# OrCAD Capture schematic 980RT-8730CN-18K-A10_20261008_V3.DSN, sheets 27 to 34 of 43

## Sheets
27 S0097_ATX_POWER: size Custom
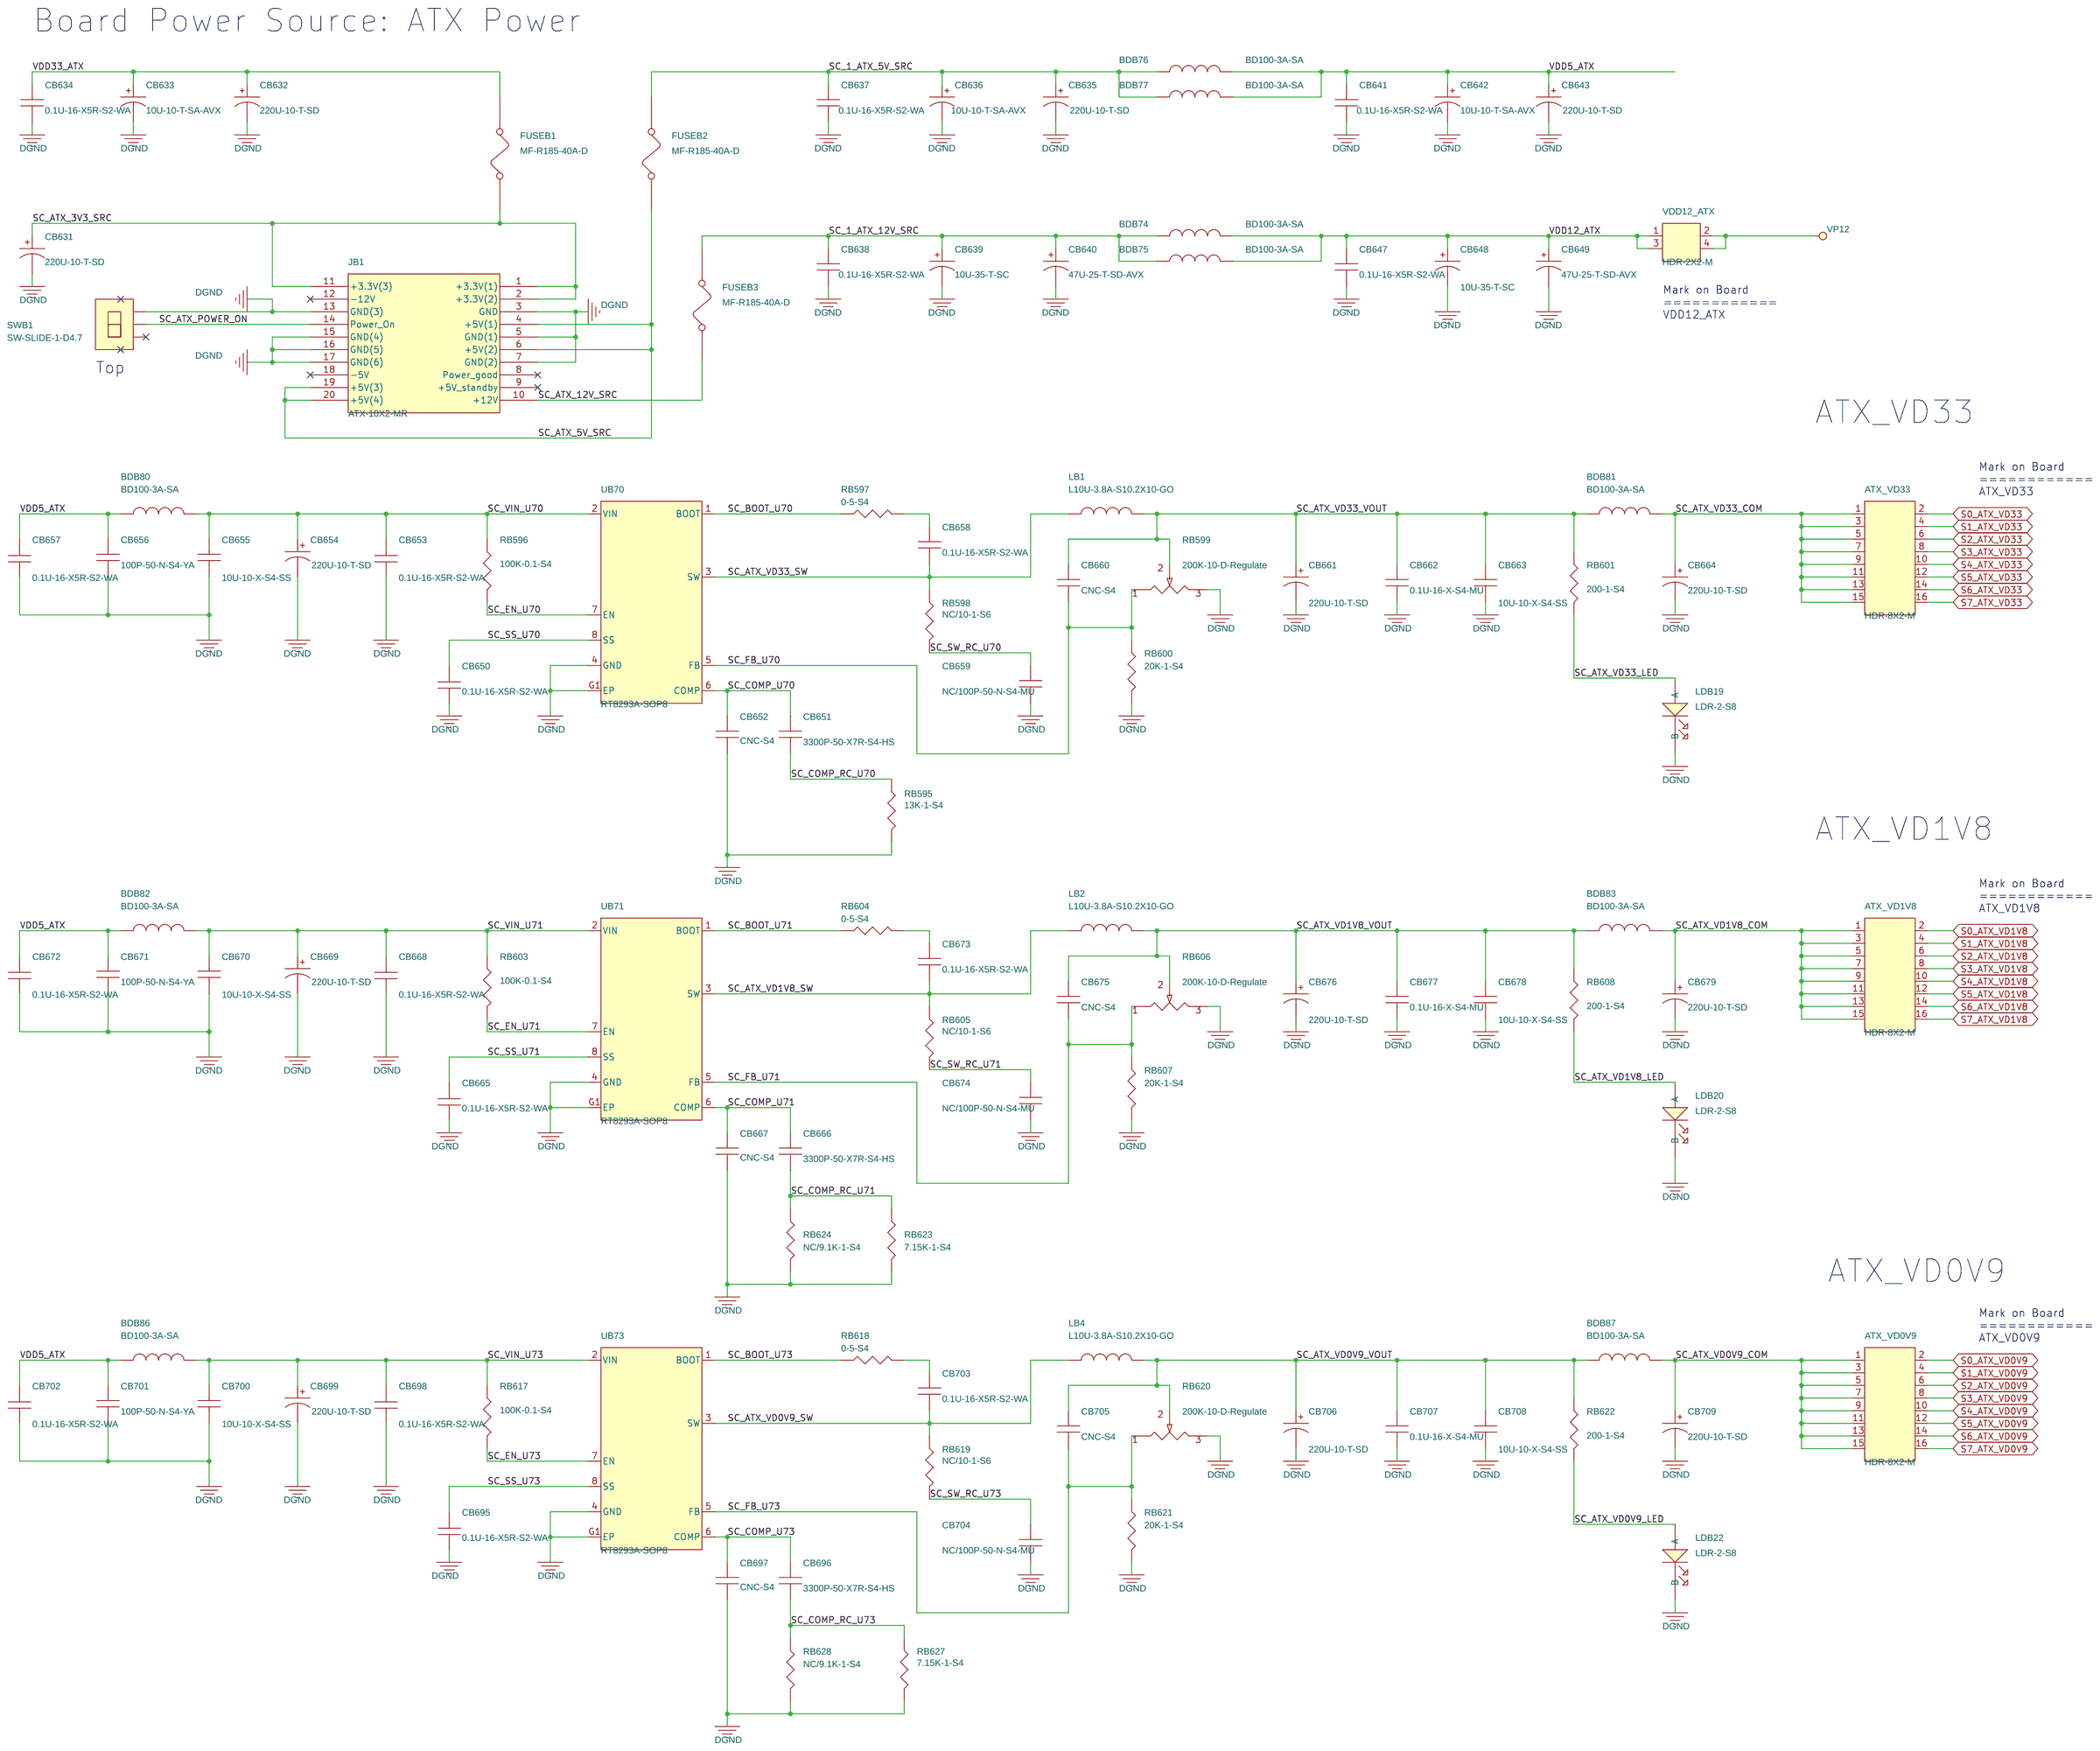
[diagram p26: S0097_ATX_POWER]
28 S0098_128UR: size A2
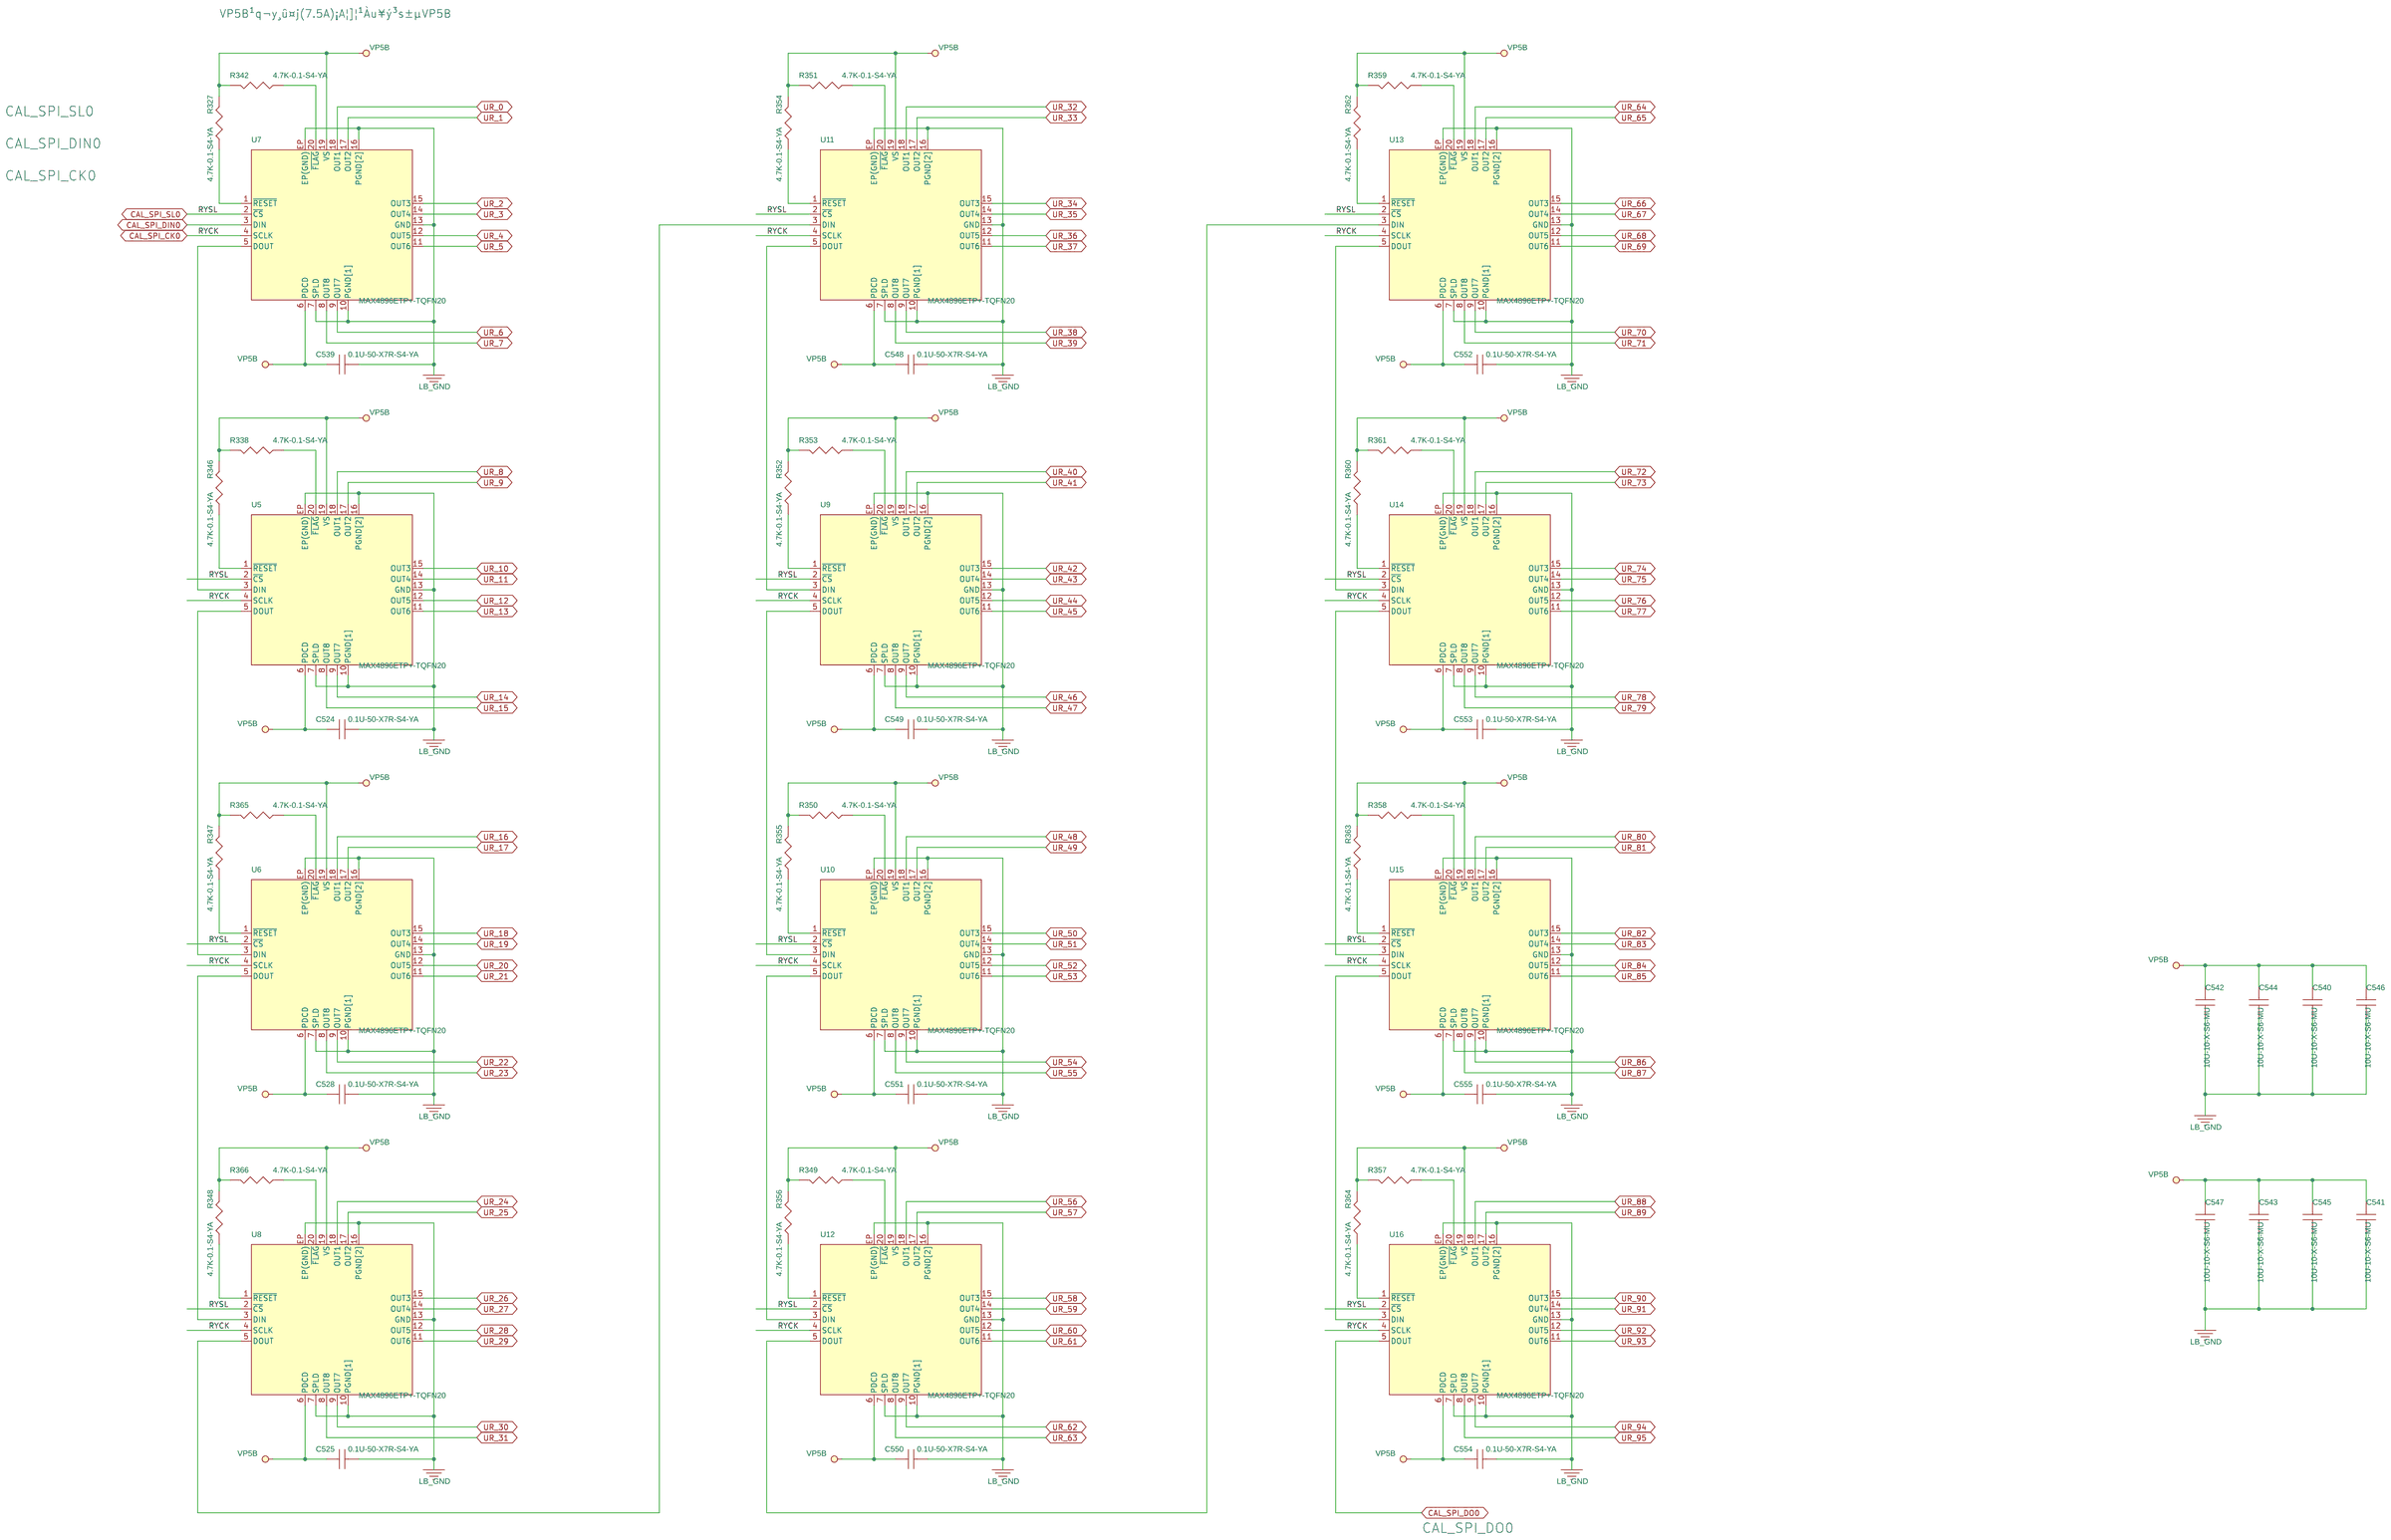
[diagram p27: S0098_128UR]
29 S0099_MISC: size A3
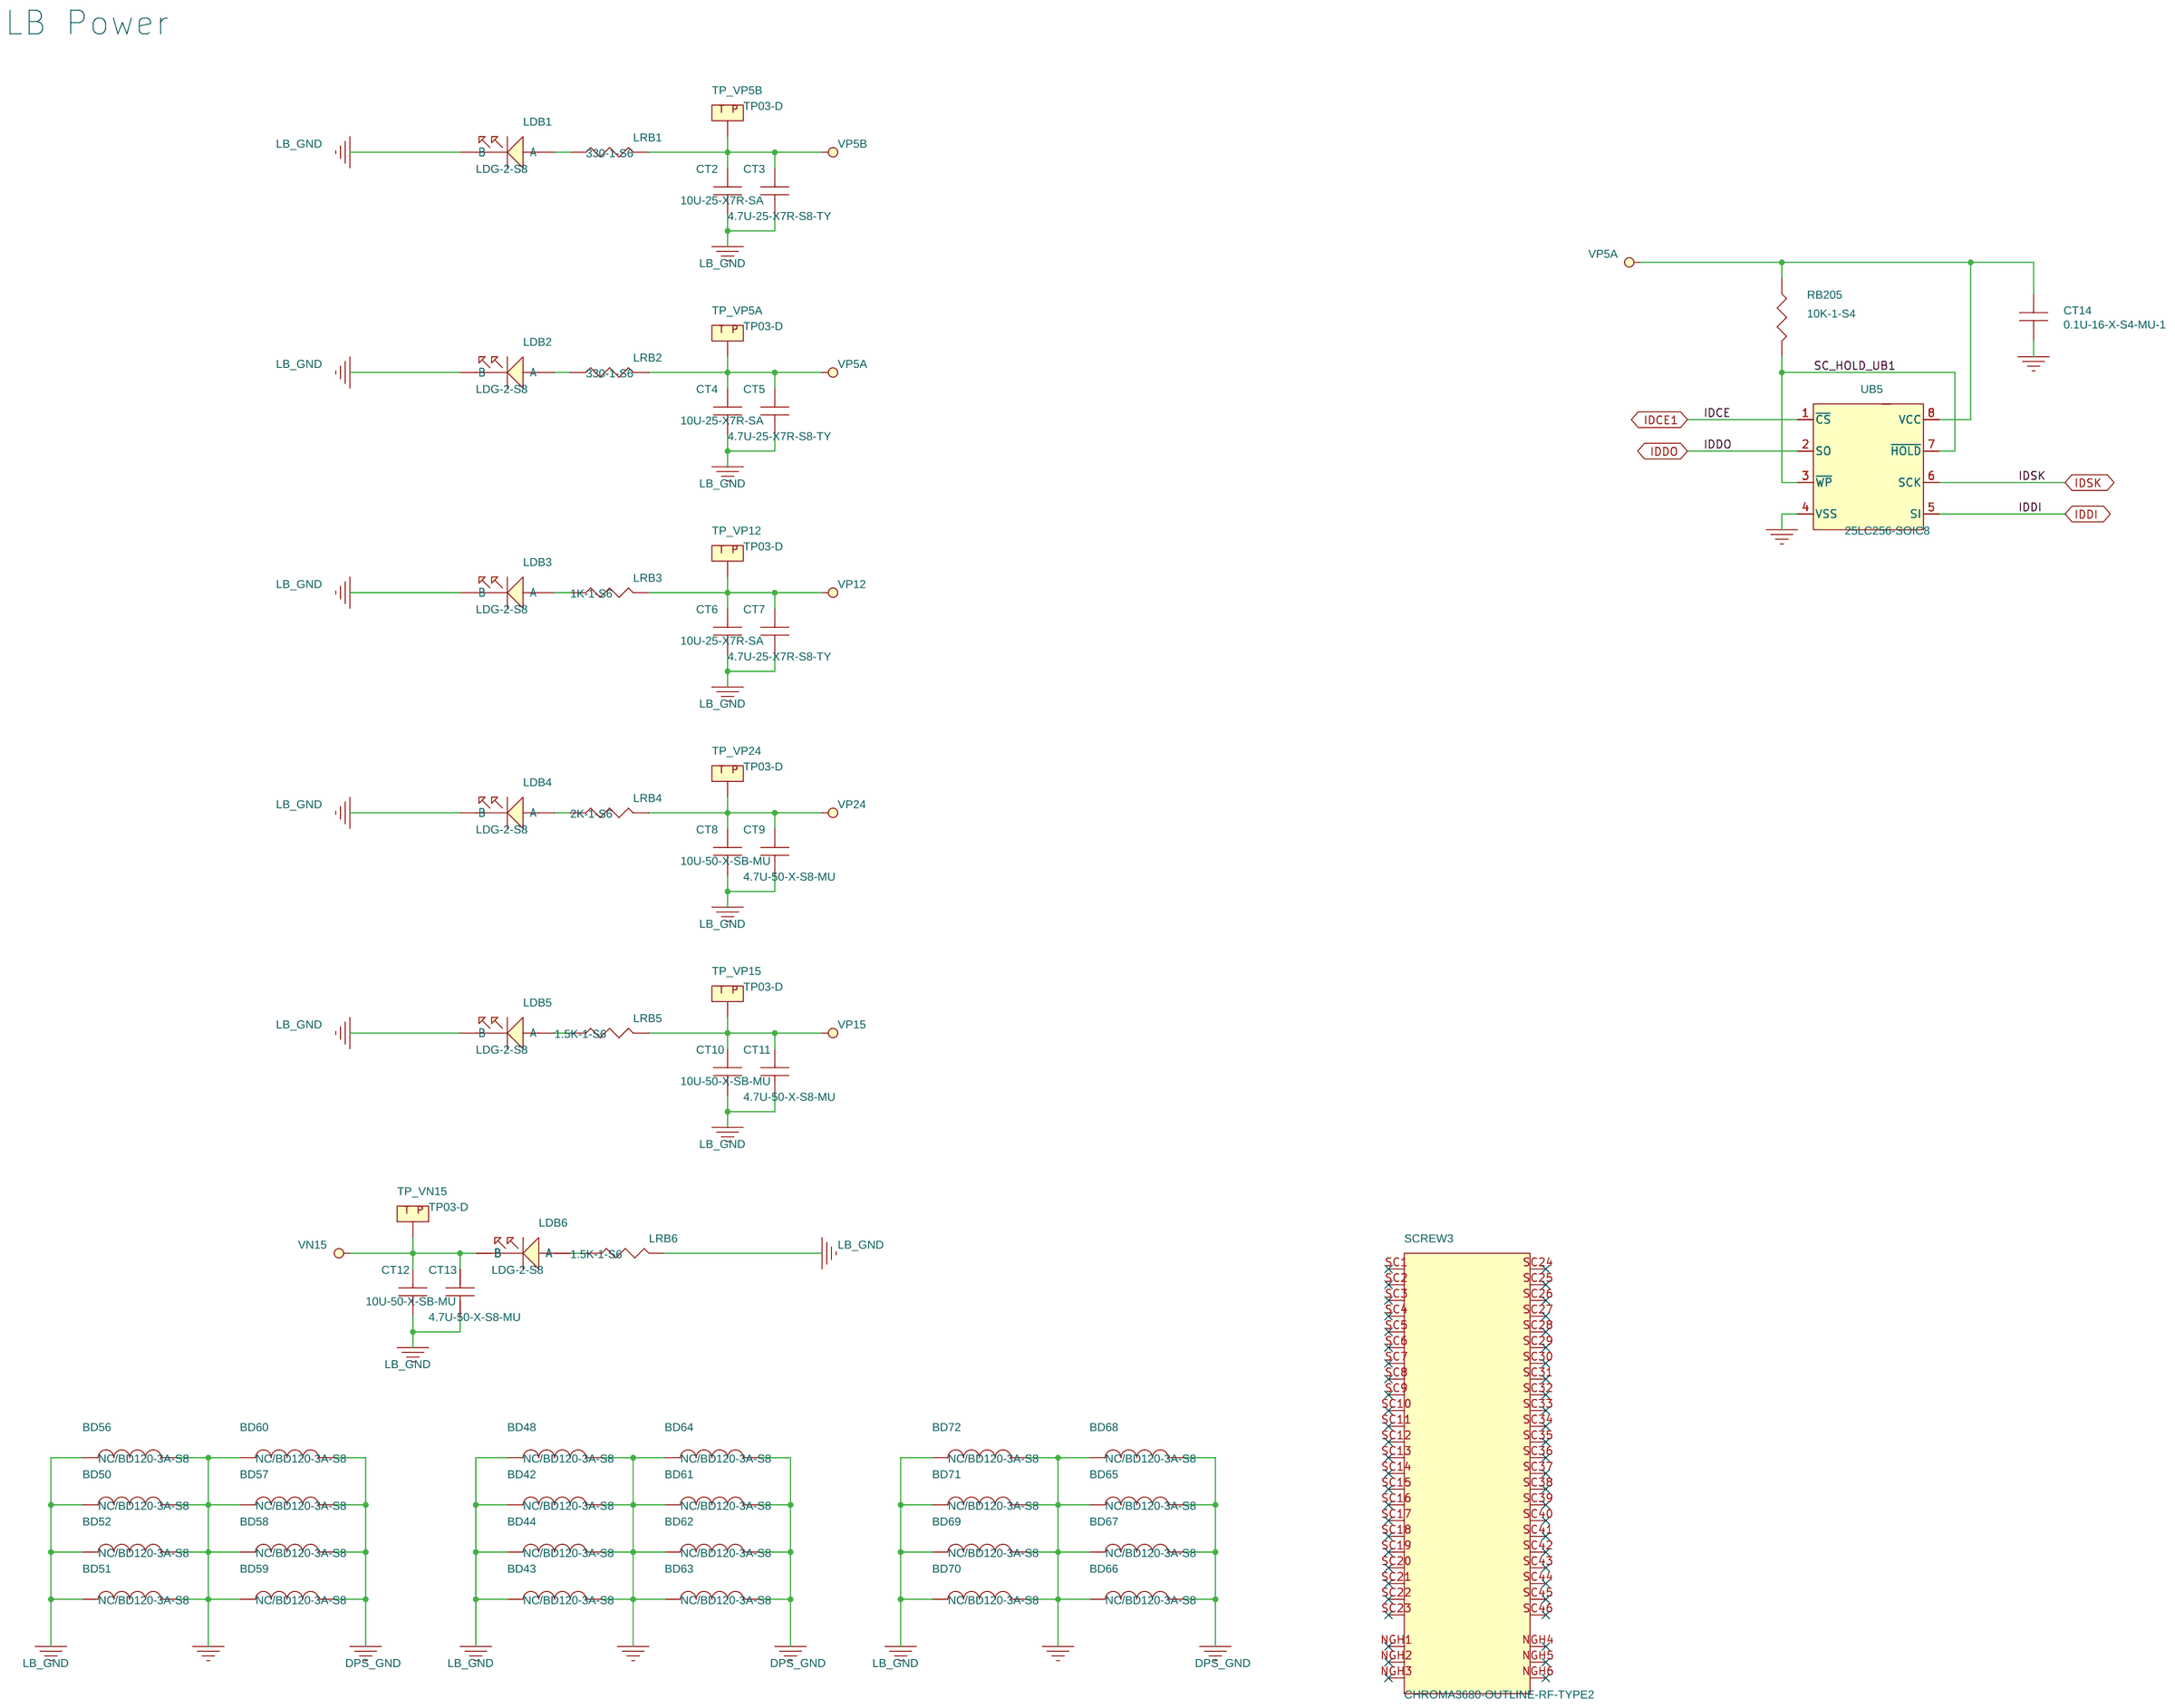
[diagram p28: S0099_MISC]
30 S9999_HOLE: size A
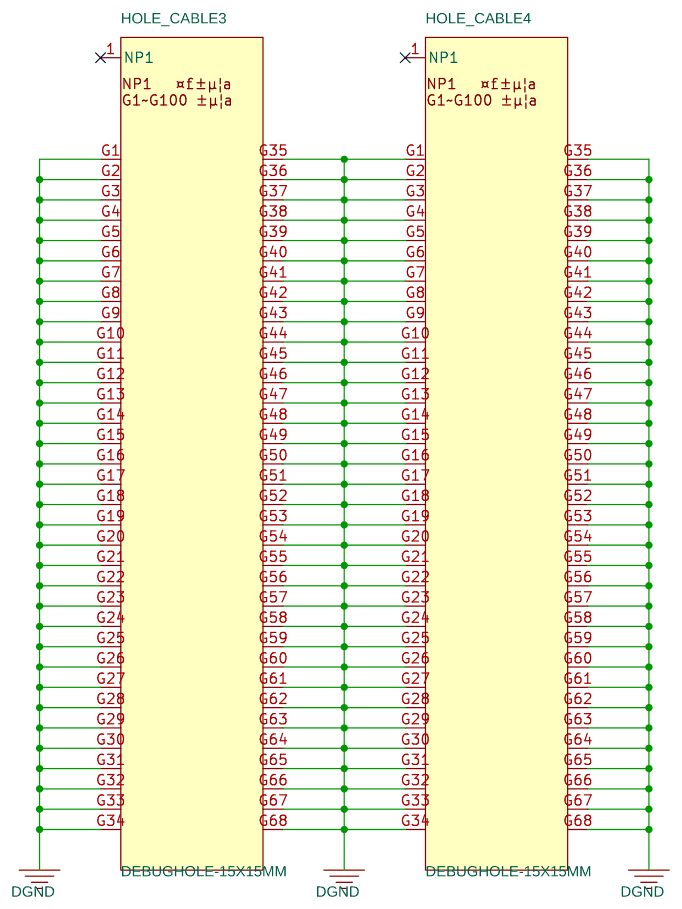
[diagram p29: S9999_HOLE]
31 T01.3680_DPS64_HDAV_H_P1: size Custom
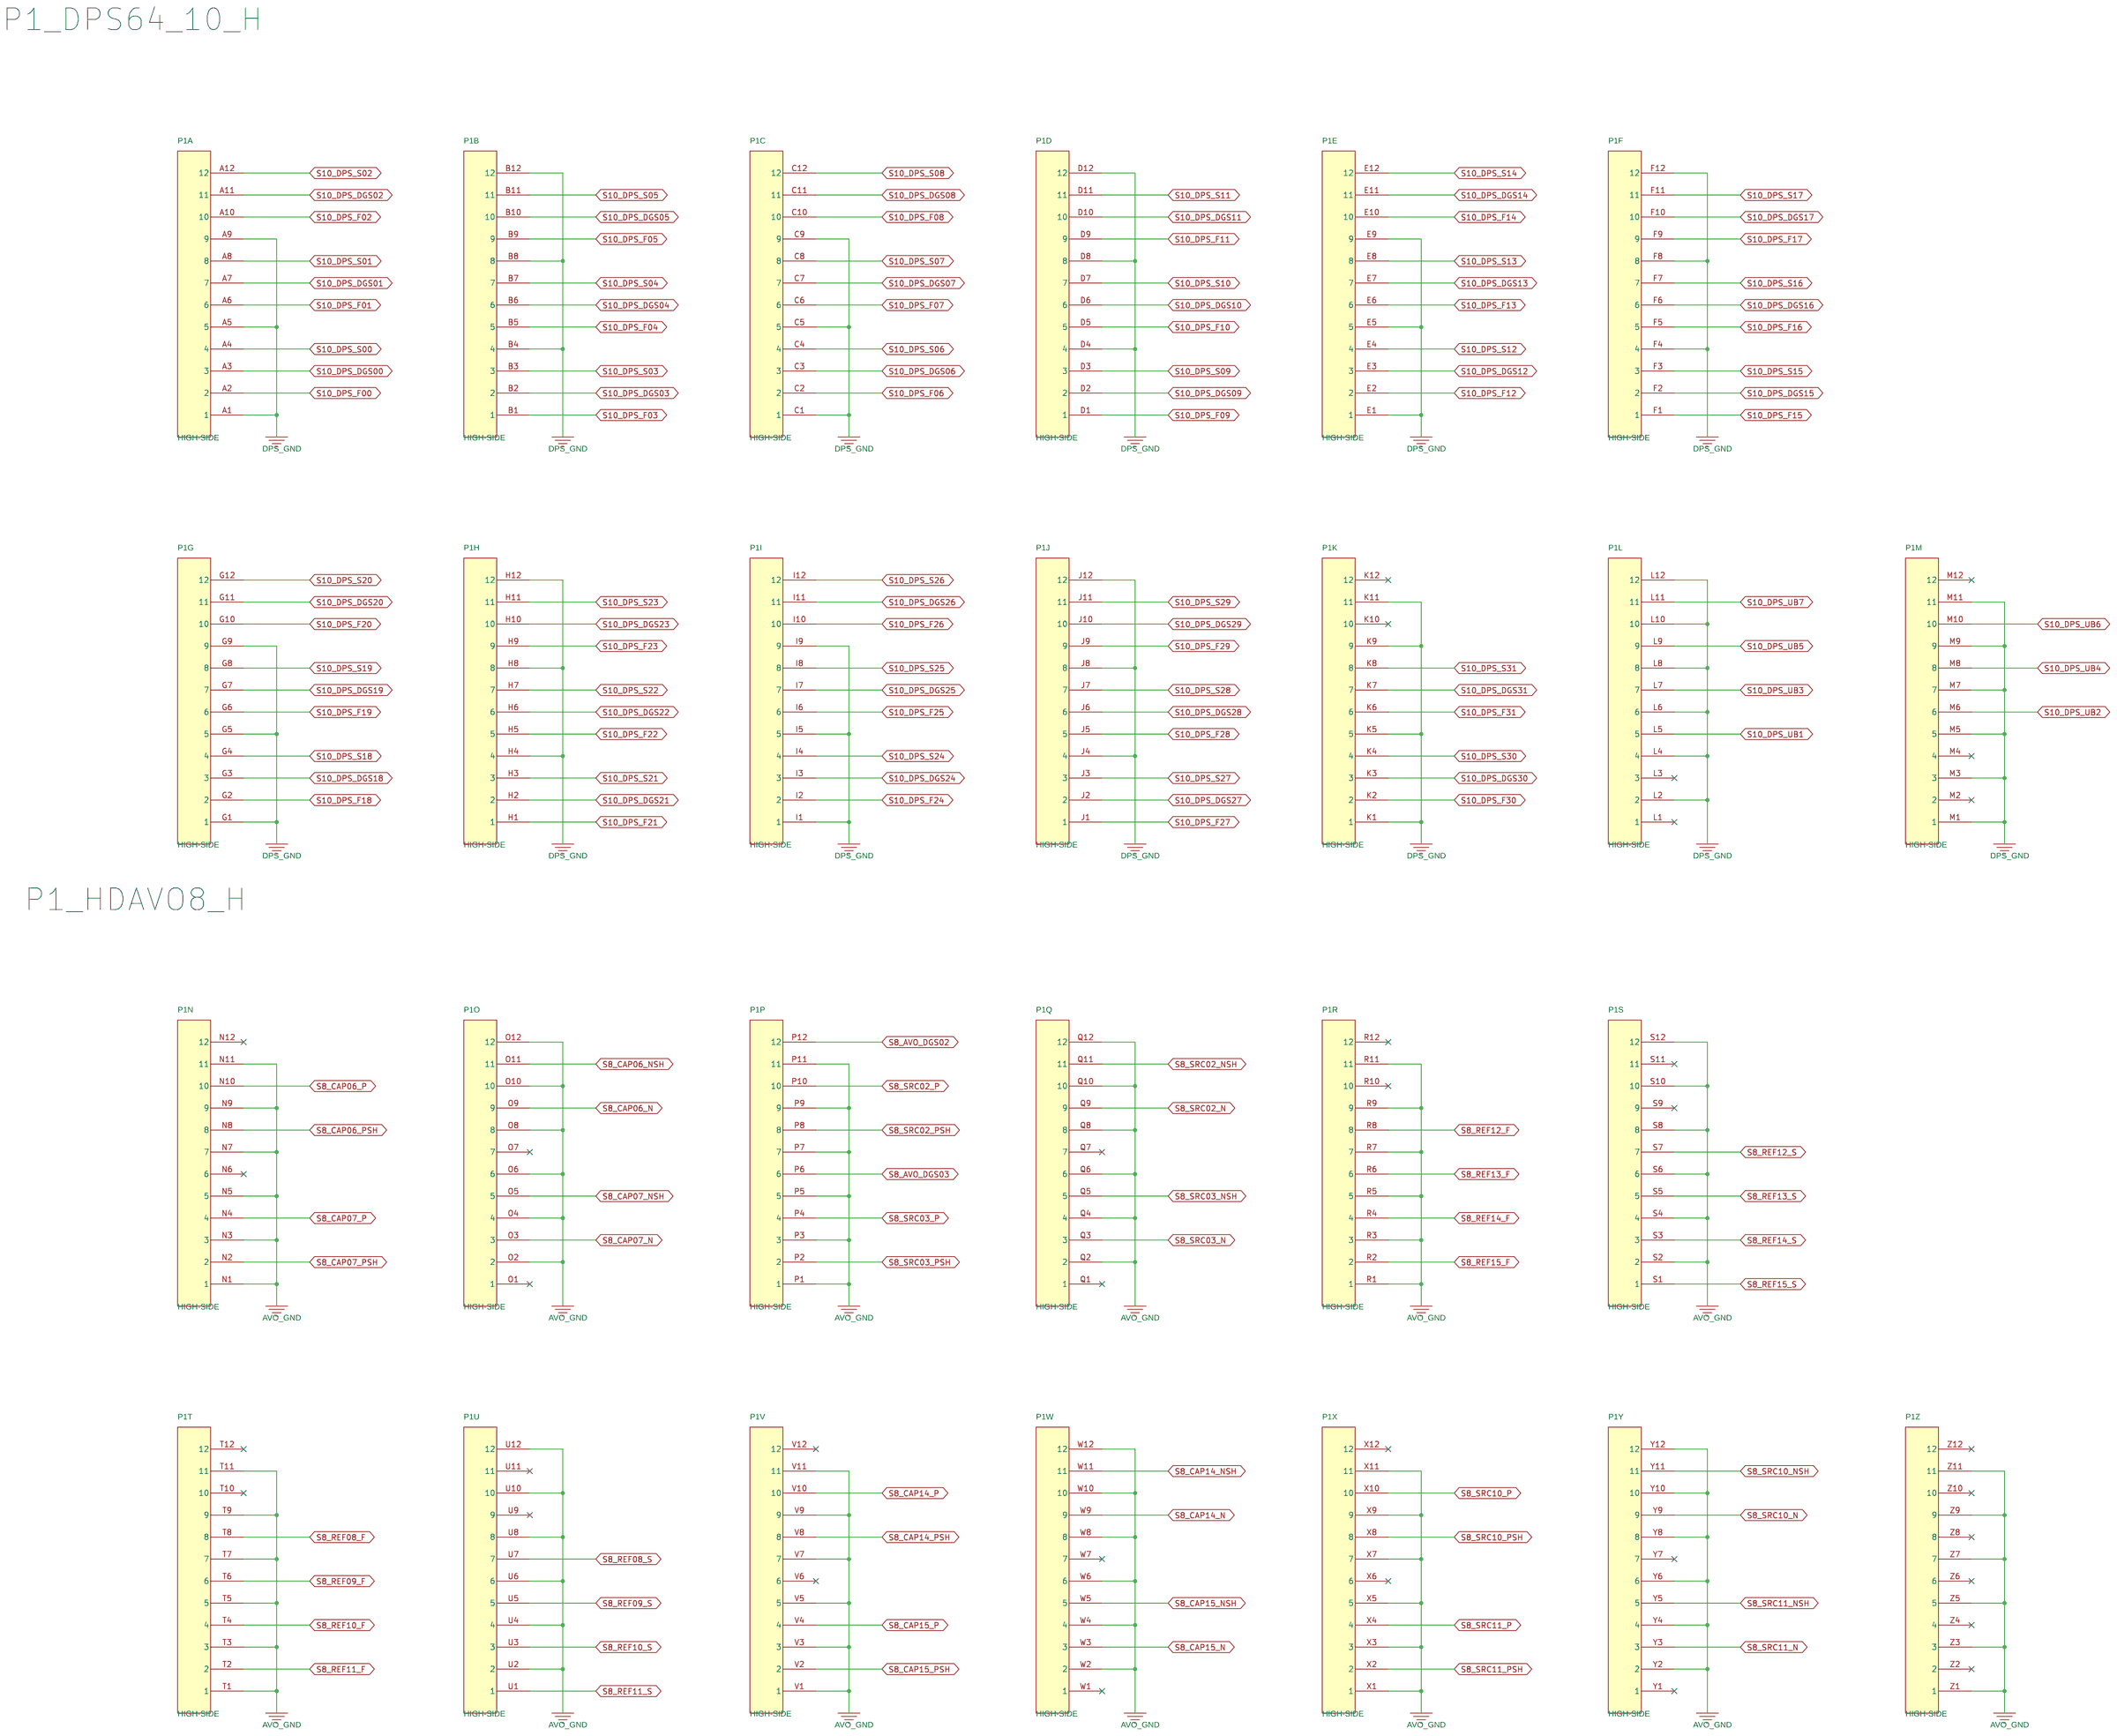
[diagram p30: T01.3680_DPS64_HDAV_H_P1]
32 T02.3680_LPC_P2: size Custom
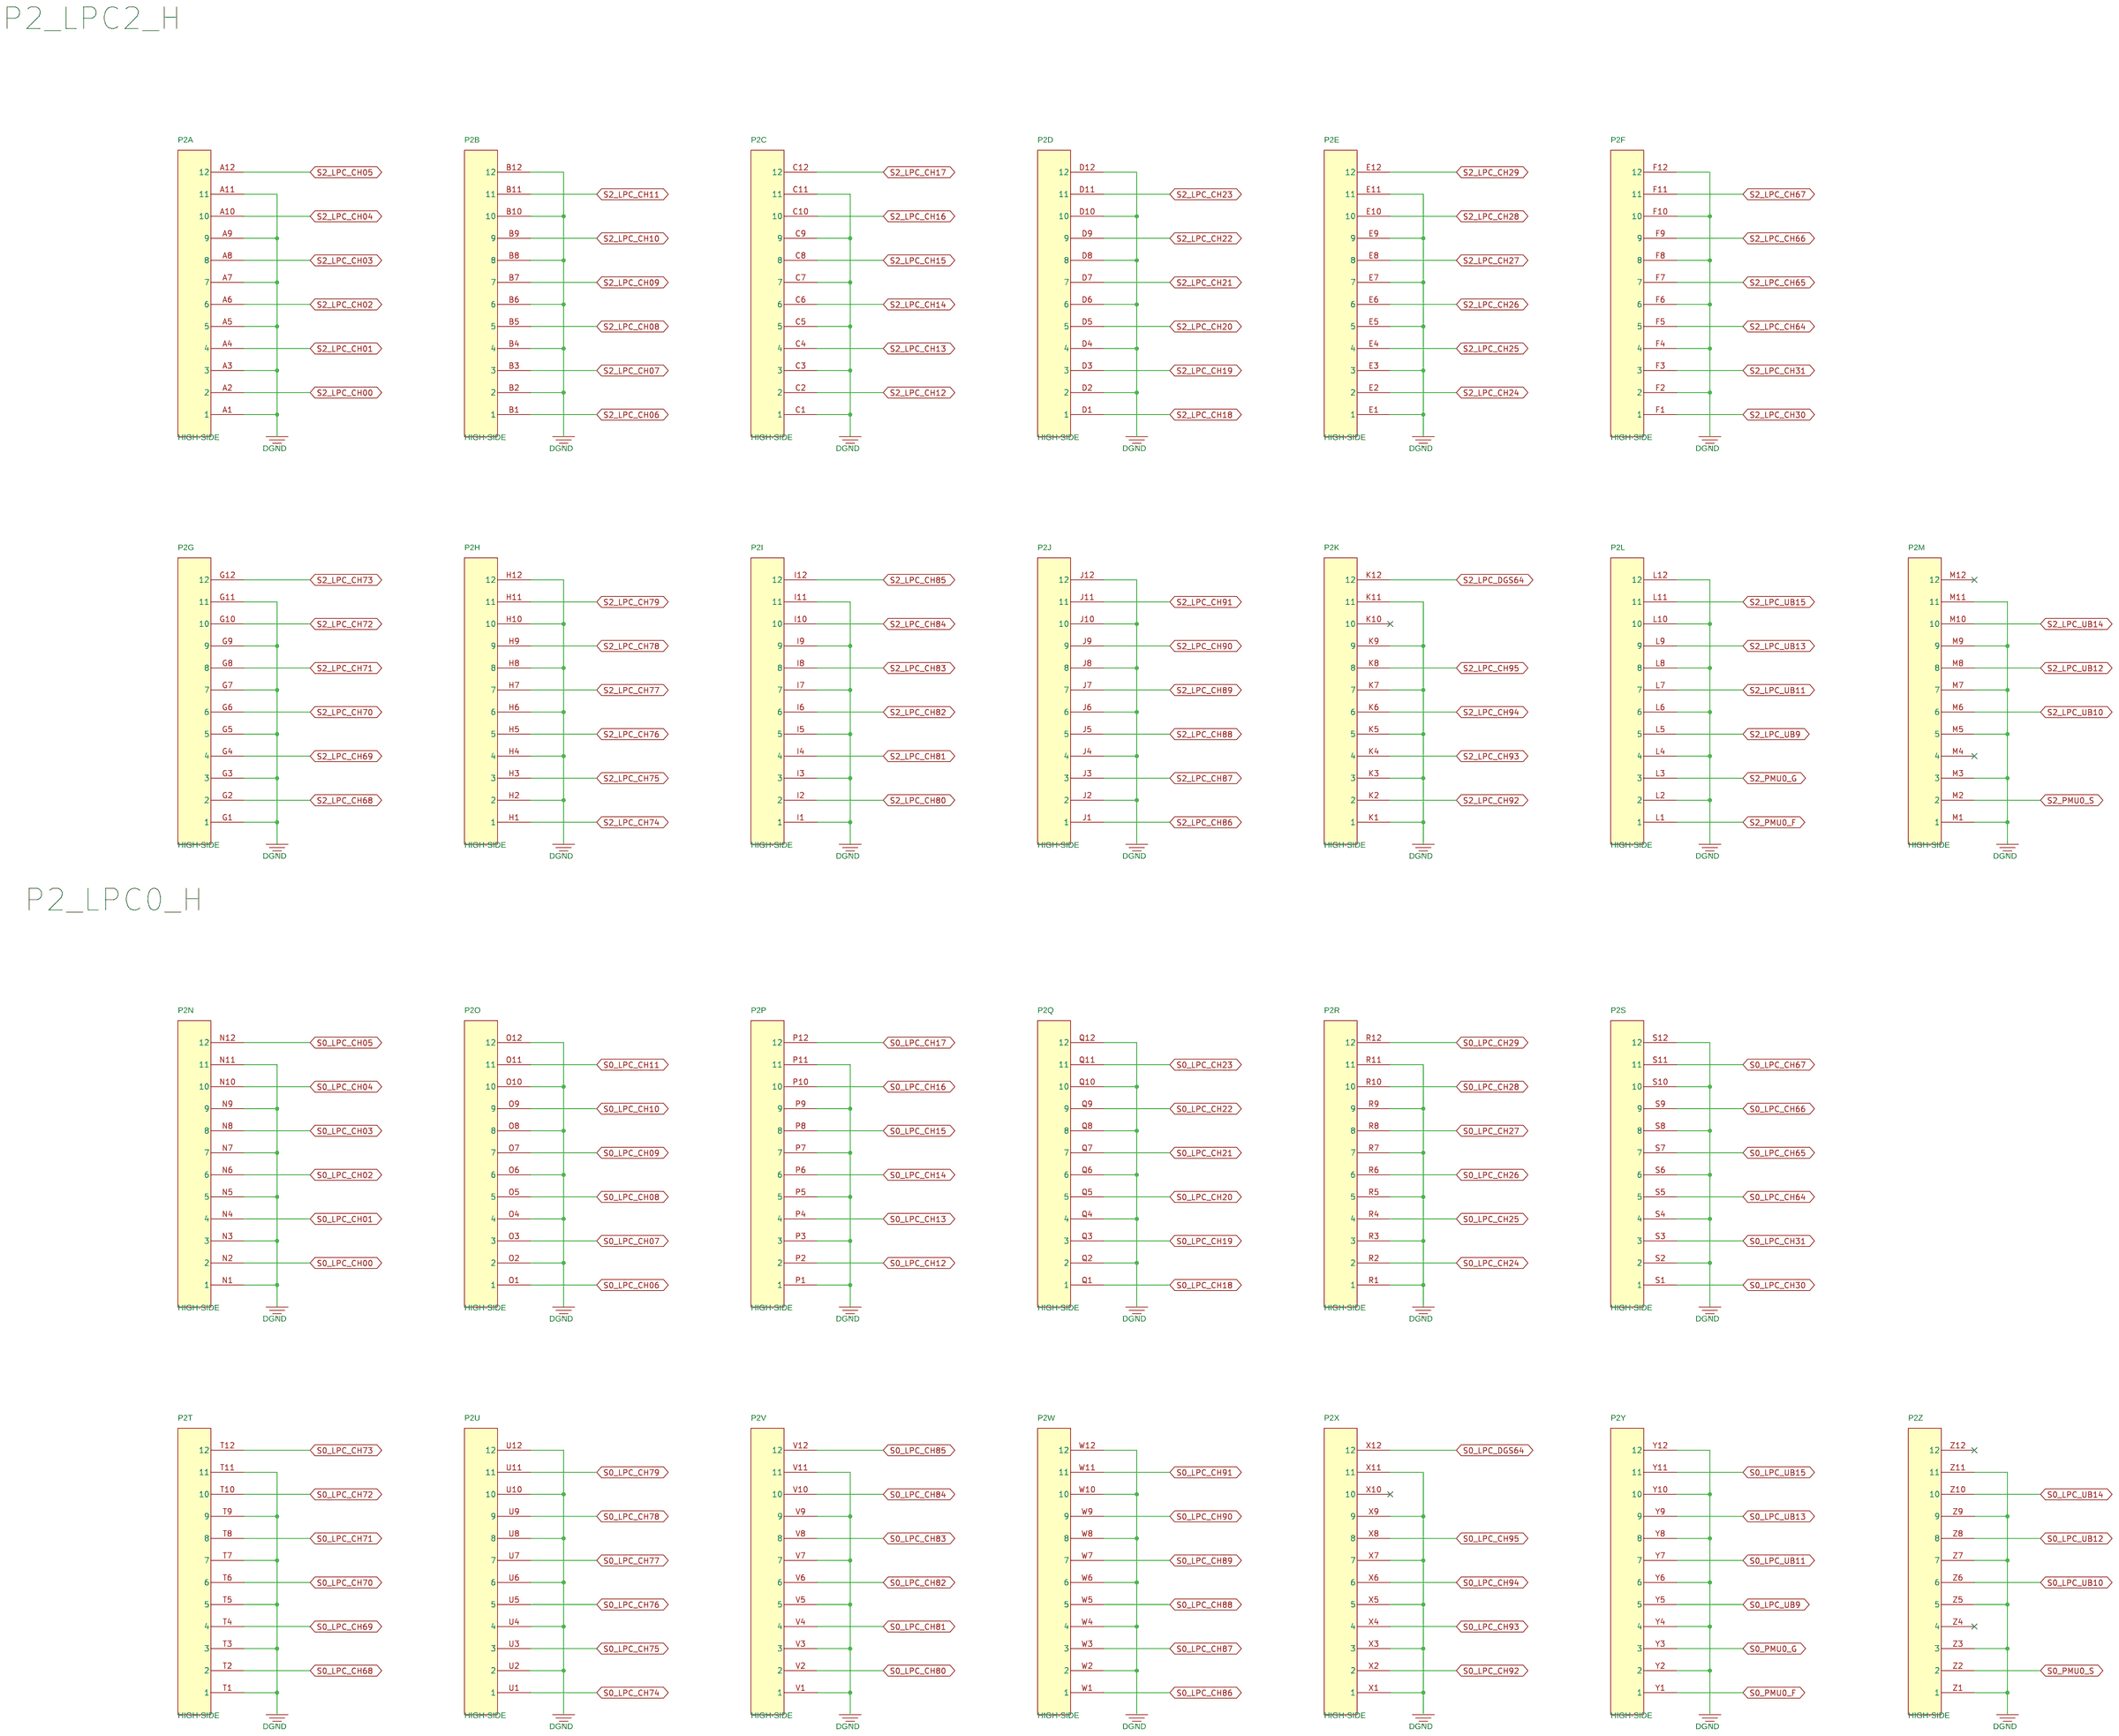
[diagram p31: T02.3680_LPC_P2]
33 T04.3680_DPS64_HDAV_H_P4: size Custom
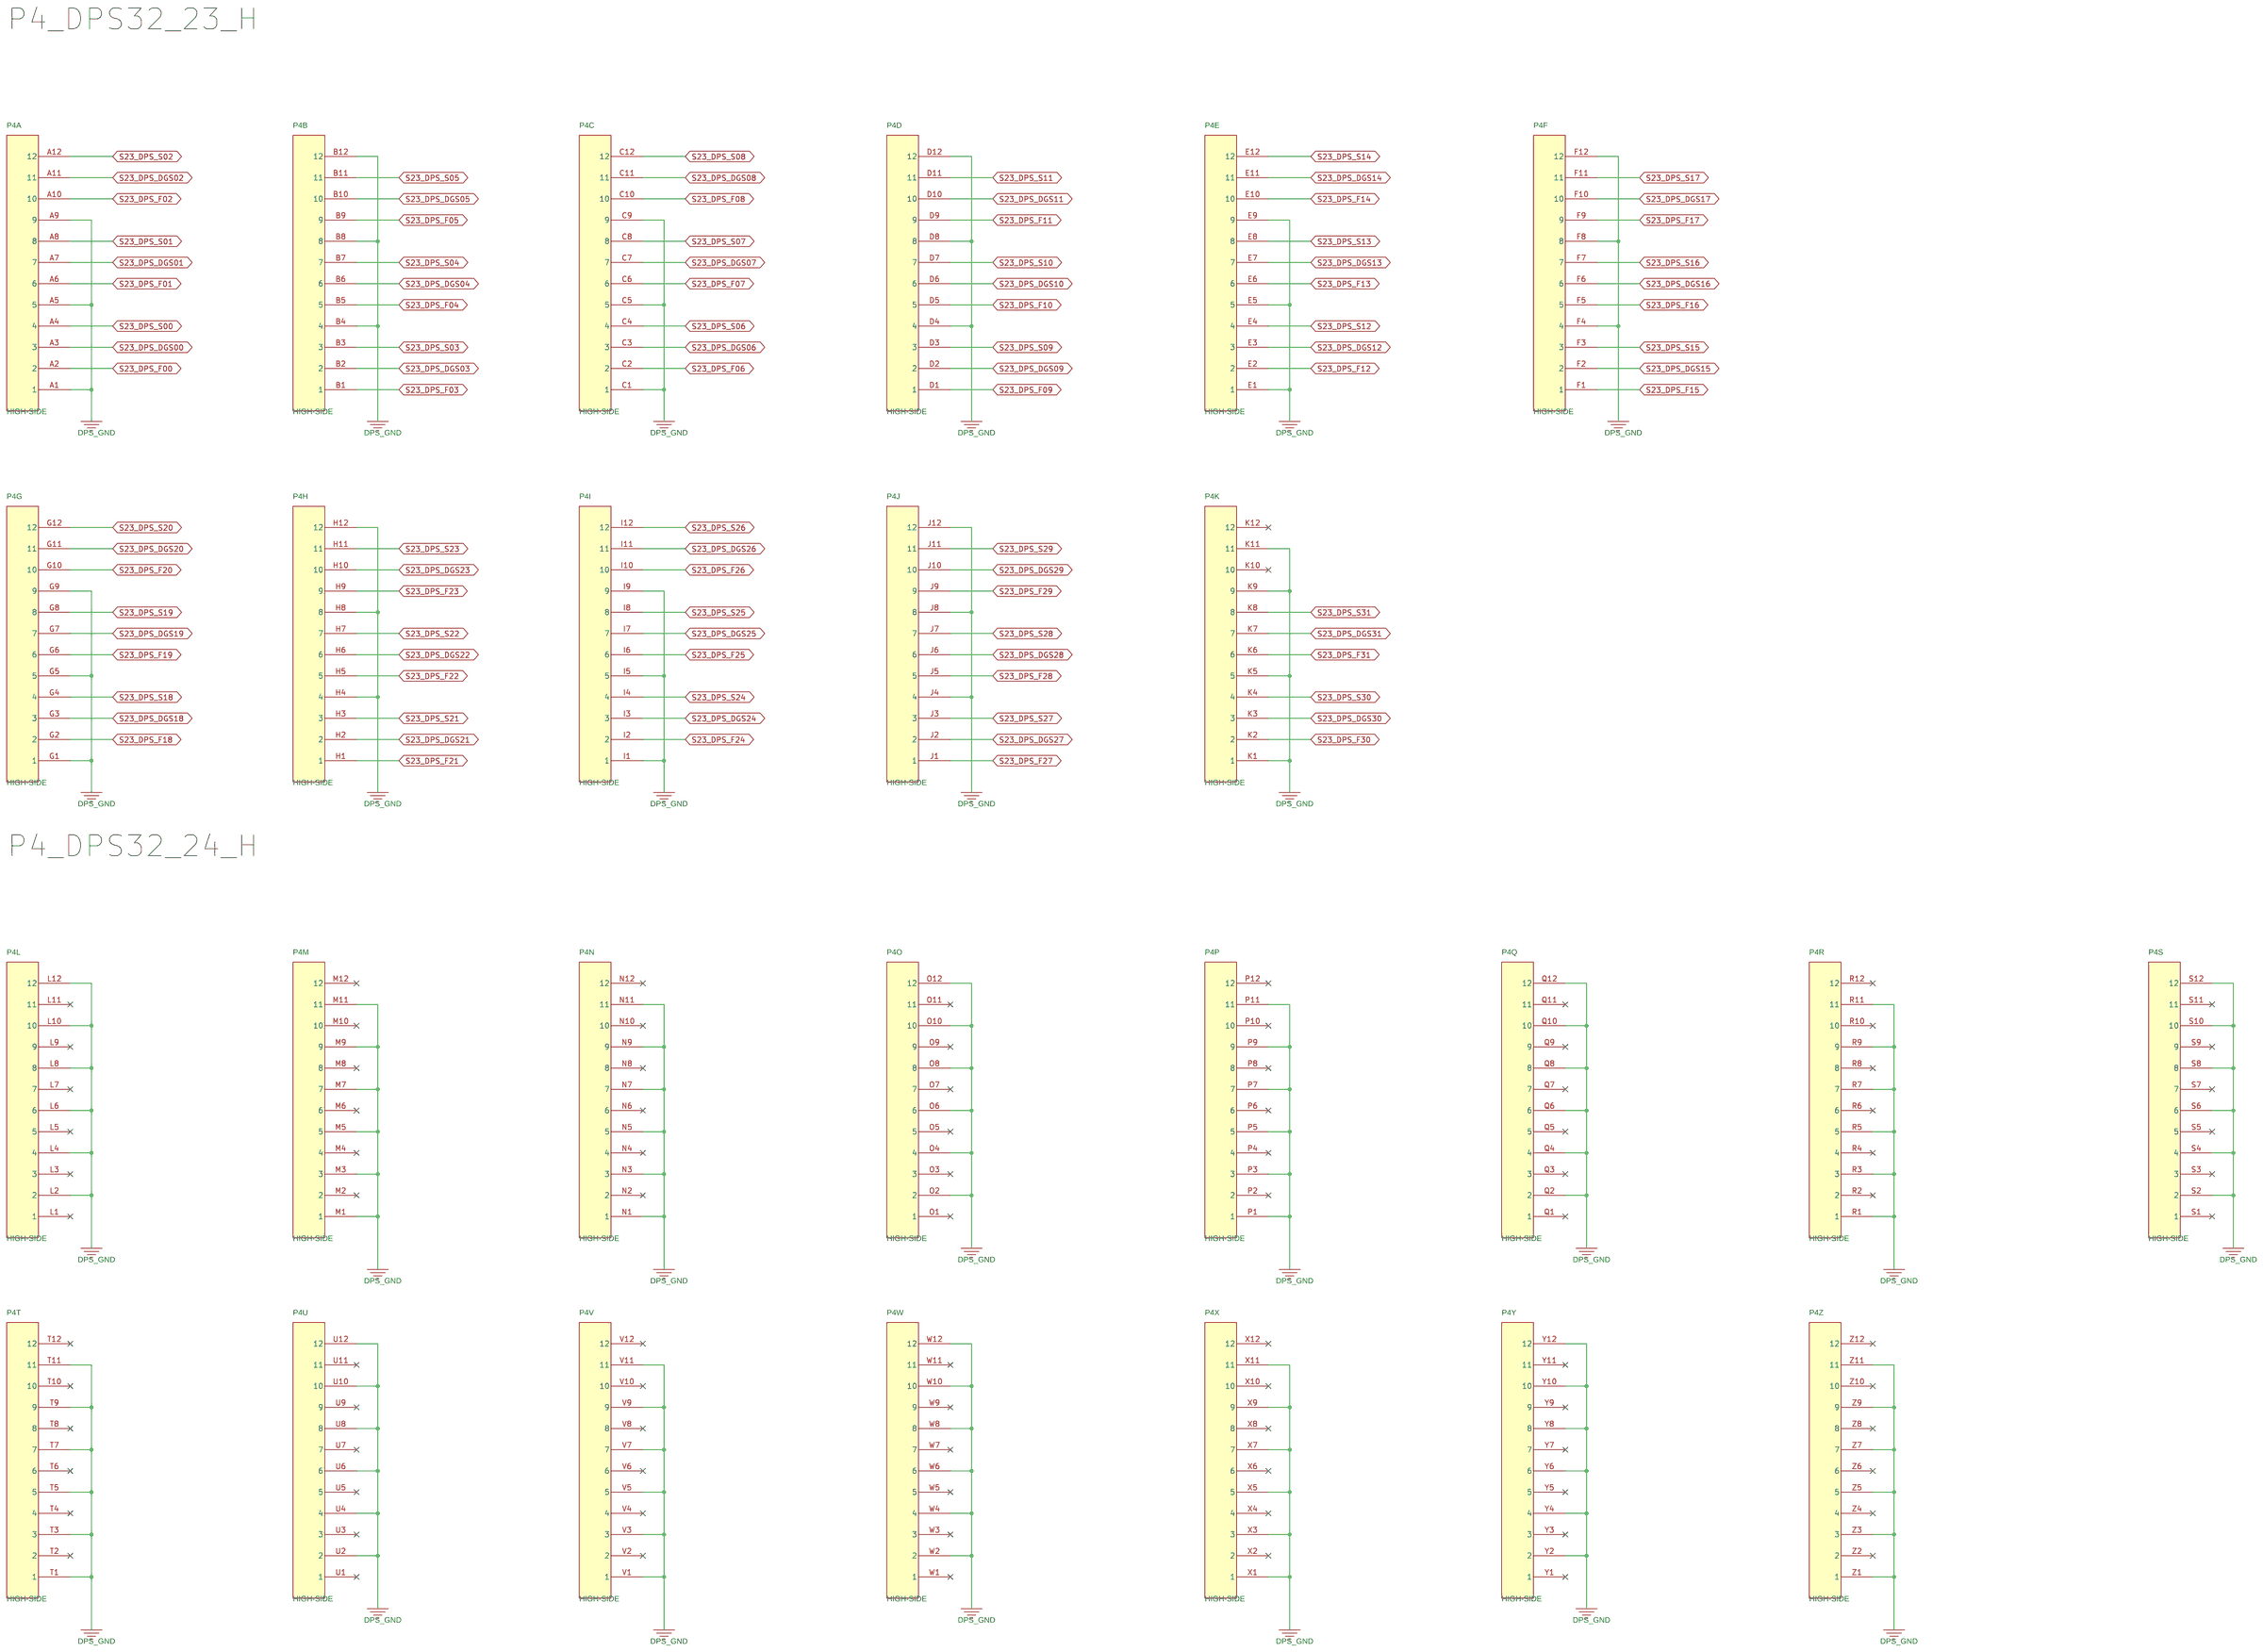
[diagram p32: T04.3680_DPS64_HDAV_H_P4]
34 T05.3680_LPC_P5: size Custom
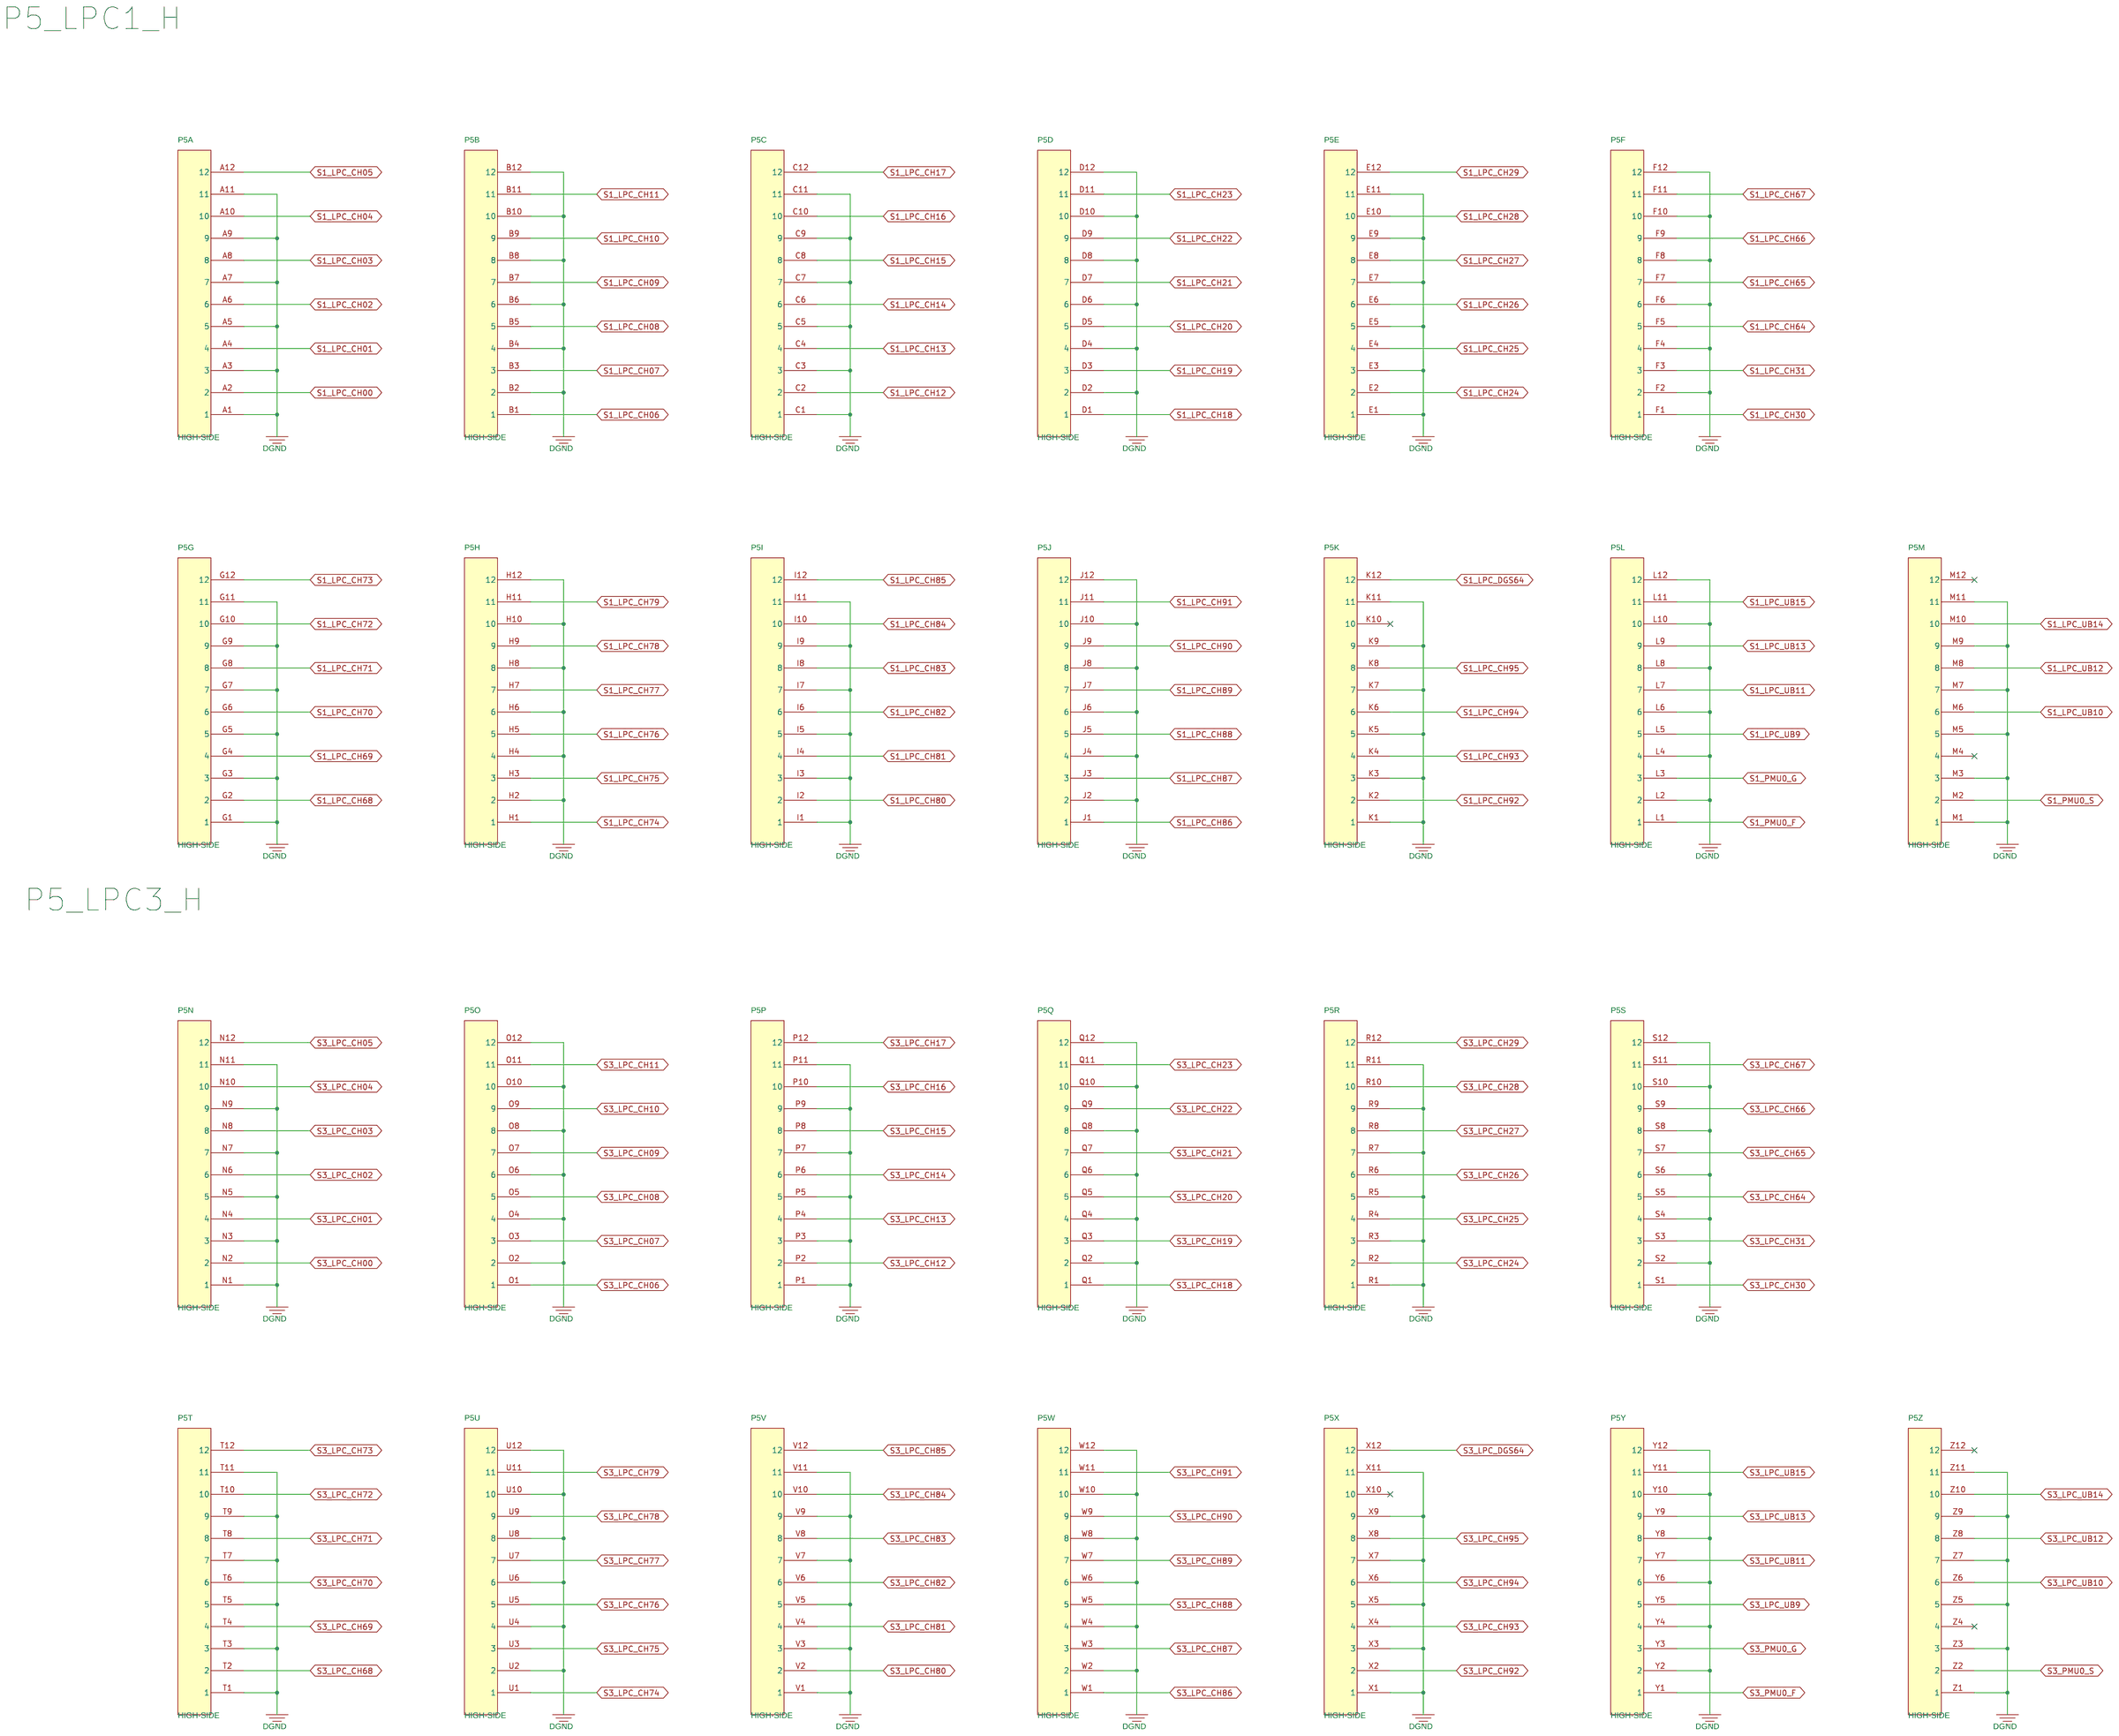
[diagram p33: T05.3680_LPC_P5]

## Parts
sheet S0097_ATX_POWER
ATX_VD0V9  HDR-8X2-M  [CONN_8X2_2P54MM_PH]
ATX_VD1V8  HDR-8X2-M  [CONN_8X2_2P54MM_PH]
ATX_VD33  HDR-8X2-M  [CONN_8X2_2P54MM_PH]
BDB74  BD100-3A-SA  [FB1206]
BDB75  BD100-3A-SA  [FB1206]
BDB76  BD100-3A-SA  [FB1206]
BDB77  BD100-3A-SA  [FB1206]
BDB80  BD100-3A-SA  [FB1206]
BDB81  BD100-3A-SA  [FB1206]
BDB82  BD100-3A-SA  [FB1206]
BDB83  BD100-3A-SA  [FB1206]
BDB86  BD100-3A-SA  [FB1206]
BDB87  BD100-3A-SA  [FB1206]
CB631  220U-10-T-SD  [CODE_D]
CB632  220U-10-T-SD  [CODE_D]
CB633  10U-10-T-SA-AVX  [CODE_A]
CB634  0.1U-16-X5R-S2-WA  [C0201]
CB635  220U-10-T-SD  [CODE_D]
CB636  10U-10-T-SA-AVX  [CODE_A]
CB637  0.1U-16-X5R-S2-WA  [C0201]
CB638  0.1U-16-X5R-S2-WA  [C0201]
CB639  10U-35-T-SC  [CODE_C]
CB640  47U-25-T-SD-AVX  [CODE_D]
CB641  0.1U-16-X5R-S2-WA  [C0201]
CB642  10U-10-T-SA-AVX  [CODE_A]
CB643  220U-10-T-SD  [CODE_D]
CB647  0.1U-16-X5R-S2-WA  [C0201]
CB648  10U-35-T-SC  [CODE_C]
CB649  47U-25-T-SD-AVX  [CODE_D]
CB650  0.1U-16-X5R-S2-WA  [C0201]
CB651  3300P-50-X7R-S4-HS  [C0402]
CB652  CNC-S4  [C0402]
CB653  0.1U-16-X5R-S2-WA  [C0201]
CB654  220U-10-T-SD  [CODE_D]
CB655  10U-10-X-S4-SS  [C0402]
CB656  100P-50-N-S4-YA  [C0402]
CB657  0.1U-16-X5R-S2-WA  [C0201]
CB658  0.1U-16-X5R-S2-WA  [C0201]
CB659  NC/100P-50-N-S4-MU  [C0402]
CB660  CNC-S4  [C0402]
CB661  220U-10-T-SD  [CODE_D]
CB662  0.1U-16-X-S4-MU  [C0402]
CB663  10U-10-X-S4-SS  [C0402]
CB664  220U-10-T-SD  [CODE_D]
CB665  0.1U-16-X5R-S2-WA  [C0201]
CB666  3300P-50-X7R-S4-HS  [C0402]
CB667  CNC-S4  [C0402]
CB668  0.1U-16-X5R-S2-WA  [C0201]
CB669  220U-10-T-SD  [CODE_D]
CB670  10U-10-X-S4-SS  [C0402]
CB671  100P-50-N-S4-YA  [C0402]
CB672  0.1U-16-X5R-S2-WA  [C0201]
CB673  0.1U-16-X5R-S2-WA  [C0201]
CB674  NC/100P-50-N-S4-MU  [C0402]
CB675  CNC-S4  [C0402]
CB676  220U-10-T-SD  [CODE_D]
CB677  0.1U-16-X-S4-MU  [C0402]
CB678  10U-10-X-S4-SS  [C0402]
CB679  220U-10-T-SD  [CODE_D]
CB695  0.1U-16-X5R-S2-WA  [C0201]
CB696  3300P-50-X7R-S4-HS  [C0402]
CB697  CNC-S4  [C0402]
CB698  0.1U-16-X5R-S2-WA  [C0201]
CB699  220U-10-T-SD  [CODE_D]
CB700  10U-10-X-S4-SS  [C0402]
CB701  100P-50-N-S4-YA  [C0402]
CB702  0.1U-16-X5R-S2-WA  [C0201]
CB703  0.1U-16-X5R-S2-WA  [C0201]
CB704  NC/100P-50-N-S4-MU  [C0402]
CB705  CNC-S4  [C0402]
CB706  220U-10-T-SD  [CODE_D]
CB707  0.1U-16-X-S4-MU  [C0402]
CB708  10U-10-X-S4-SS  [C0402]
CB709  220U-10-T-SD  [CODE_D]
FUSEB1  MF-R185-40A-D  [FUSE_12X9P2MM]
FUSEB2  MF-R185-40A-D  [FUSE_12X9P2MM]
FUSEB3  MF-R185-40A-D  [FUSE_12X9P2MM]
JB1  ATX-10X2-MR  [CONN_PWR10X2_4P2MM_ML]
LB1  L10U-3.8A-S10.2X10-GO  [IND_GSSR2104]
LB2  L10U-3.8A-S10.2X10-GO  [IND_GSSR2104]
LB4  L10U-3.8A-S10.2X10-GO  [IND_GSSR2104]
LDB19  LDR-2-S8  [LED_0805]
LDB20  LDR-2-S8  [LED_0805]
LDB22  LDR-2-S8  [LED_0805]
RB595  13K-1-S4  [R0402]
RB596  100K-0.1-S4  [R0402]
RB597  0-5-S4  [R0402]
RB598  NC/10-1-S6  [R0603]
RB599  200K-10-D-Regulate  [VRD_3296W_BOURNS_SKPIN]
RB600  20K-1-S4  [R0402]
RB601  200-1-S4  [R0402]
RB603  100K-0.1-S4  [R0402]
RB604  0-5-S4  [R0402]
RB605  NC/10-1-S6  [R0603]
RB606  200K-10-D-Regulate  [VRD_3296W_BOURNS_SKPIN]
RB607  20K-1-S4  [R0402]
RB608  200-1-S4  [R0402]
RB617  100K-0.1-S4  [R0402]
RB618  0-5-S4  [R0402]
RB619  NC/10-1-S6  [R0603]
RB620  200K-10-D-Regulate  [VRD_3296W_BOURNS_SKPIN]
RB621  20K-1-S4  [R0402]
RB622  200-1-S4  [R0402]
RB623  7.15K-1-S4  [R0402]
RB624  NC/9.1K-1-S4  [R0402]
RB627  7.15K-1-S4  [R0402]
RB628  NC/9.1K-1-S4  [R0402]
SWB1  SW-SLIDE-1-D4.7  [SW_5P_UTP0030B]
UB70  RT8293A-SOP8  [SO8_206X127MM_G]
UB71  RT8293A-SOP8  [SO8_206X127MM_G]
UB73  RT8293A-SOP8  [SO8_206X127MM_G]
VDD12_ATX  HDR-2X2-M  [CONN_2X2_2P54MM_PH]
sheet S0098_128UR
C524  0.1U-50-X7R-S4-YA  [C0402]
C525  0.1U-50-X7R-S4-YA  [C0402]
C528  0.1U-50-X7R-S4-YA  [C0402]
C539  0.1U-50-X7R-S4-YA  [C0402]
C540  10U-10-X-S6-MU  [C0603]
C541  10U-10-X-S6-MU  [C0603]
C542  10U-10-X-S6-MU  [C0603]
C543  10U-10-X-S6-MU  [C0603]
C544  10U-10-X-S6-MU  [C0603]
C545  10U-10-X-S6-MU  [C0603]
C546  10U-10-X-S6-MU  [C0603]
C547  10U-10-X-S6-MU  [C0603]
C548  0.1U-50-X7R-S4-YA  [C0402]
C549  0.1U-50-X7R-S4-YA  [C0402]
C550  0.1U-50-X7R-S4-YA  [C0402]
C551  0.1U-50-X7R-S4-YA  [C0402]
C552  0.1U-50-X7R-S4-YA  [C0402]
C553  0.1U-50-X7R-S4-YA  [C0402]
C554  0.1U-50-X7R-S4-YA  [C0402]
C555  0.1U-50-X7R-S4-YA  [C0402]
R327  4.7K-0.1-S4-YA  [R0402]
R338  4.7K-0.1-S4-YA  [R0402]
R342  4.7K-0.1-S4-YA  [R0402]
R346  4.7K-0.1-S4-YA  [R0402]
R347  4.7K-0.1-S4-YA  [R0402]
R348  4.7K-0.1-S4-YA  [R0402]
R349  4.7K-0.1-S4-YA  [R0402]
R350  4.7K-0.1-S4-YA  [R0402]
R351  4.7K-0.1-S4-YA  [R0402]
R352  4.7K-0.1-S4-YA  [R0402]
R353  4.7K-0.1-S4-YA  [R0402]
R354  4.7K-0.1-S4-YA  [R0402]
R355  4.7K-0.1-S4-YA  [R0402]
R356  4.7K-0.1-S4-YA  [R0402]
R357  4.7K-0.1-S4-YA  [R0402]
R358  4.7K-0.1-S4-YA  [R0402]
R359  4.7K-0.1-S4-YA  [R0402]
R360  4.7K-0.1-S4-YA  [R0402]
R361  4.7K-0.1-S4-YA  [R0402]
R362  4.7K-0.1-S4-YA  [R0402]
R363  4.7K-0.1-S4-YA  [R0402]
R364  4.7K-0.1-S4-YA  [R0402]
R365  4.7K-0.1-S4-YA  [R0402]
R366  4.7K-0.1-S4-YA  [R0402]
U5  MAX4896ETP+-TQFN20  [TQFN5X5_20P_0P65mm_G_V2]
U6  MAX4896ETP+-TQFN20  [TQFN5X5_20P_0P65mm_G_V2]
U7  MAX4896ETP+-TQFN20  [TQFN5X5_20P_0P65mm_G_V2]
U8  MAX4896ETP+-TQFN20  [TQFN5X5_20P_0P65mm_G_V2]
U9  MAX4896ETP+-TQFN20  [TQFN5X5_20P_0P65mm_G_V2]
U10  MAX4896ETP+-TQFN20  [TQFN5X5_20P_0P65mm_G_V2]
U11  MAX4896ETP+-TQFN20  [TQFN5X5_20P_0P65mm_G_V2]
U12  MAX4896ETP+-TQFN20  [TQFN5X5_20P_0P65mm_G_V2]
U13  MAX4896ETP+-TQFN20  [TQFN5X5_20P_0P65mm_G_V2]
U14  MAX4896ETP+-TQFN20  [TQFN5X5_20P_0P65mm_G_V2]
U15  MAX4896ETP+-TQFN20  [TQFN5X5_20P_0P65mm_G_V2]
U16  MAX4896ETP+-TQFN20  [TQFN5X5_20P_0P65mm_G_V2]
sheet S0099_MISC
BD42  NC/BD120-3A-S8  [FB0805]
BD43  NC/BD120-3A-S8  [FB0805]
BD44  NC/BD120-3A-S8  [FB0805]
BD48  NC/BD120-3A-S8  [FB0805]
BD50  NC/BD120-3A-S8  [FB0805]
BD51  NC/BD120-3A-S8  [FB0805]
BD52  NC/BD120-3A-S8  [FB0805]
BD56  NC/BD120-3A-S8  [FB0805]
BD57  NC/BD120-3A-S8  [FB0805]
BD58  NC/BD120-3A-S8  [FB0805]
BD59  NC/BD120-3A-S8  [FB0805]
BD60  NC/BD120-3A-S8  [FB0805]
BD61  NC/BD120-3A-S8  [FB0805]
BD62  NC/BD120-3A-S8  [FB0805]
BD63  NC/BD120-3A-S8  [FB0805]
BD64  NC/BD120-3A-S8  [FB0805]
BD65  NC/BD120-3A-S8  [FB0805]
BD66  NC/BD120-3A-S8  [FB0805]
BD67  NC/BD120-3A-S8  [FB0805]
BD68  NC/BD120-3A-S8  [FB0805]
BD69  NC/BD120-3A-S8  [FB0805]
BD70  NC/BD120-3A-S8  [FB0805]
BD71  NC/BD120-3A-S8  [FB0805]
BD72  NC/BD120-3A-S8  [FB0805]
CT2  10U-25-X7R-SA  [C1206]
CT3  4.7U-25-X7R-S8-TY  [C0805]
CT4  10U-25-X7R-SA  [C1206]
CT5  4.7U-25-X7R-S8-TY  [C0805]
CT6  10U-25-X7R-SA  [C1206]
CT7  4.7U-25-X7R-S8-TY  [C0805]
CT8  10U-50-X-SB-MU  [C1210]
CT9  4.7U-50-X-S8-MU  [C0805]
CT10  10U-50-X-SB-MU  [C1210]
CT11  4.7U-50-X-S8-MU  [C0805]
CT12  10U-50-X-SB-MU  [C1210]
CT13  4.7U-50-X-S8-MU  [C0805]
CT14  0.1U-16-X-S4-MU-1  [C0402]
LDB1  LDG-2-S8  [LED_0805]
LDB2  LDG-2-S8  [LED_0805]
LDB3  LDG-2-S8  [LED_0805]
LDB4  LDG-2-S8  [LED_0805]
LDB5  LDG-2-S8  [LED_0805]
LDB6  LDG-2-S8  [LED_0805]
LRB1  330-1-S6  [R0603]
LRB2  330-1-S6  [R0603]
LRB3  1K-1-S6  [R0603]
LRB4  2K-1-S6  [R0603]
LRB5  1.5K-1-S6  [R0603]
LRB6  1.5K-1-S6  [R0603]
RB205  10K-1-S4  [R0402]
SCREW3  CHROMA3680-OUTLINE-RF-TYPE2  [PG_3680_FT_RF_OUTLINE_CHROMA_V2]
TP_VN15  TP03-D  [TP_060_040]
TP_VP5A  TP03-D  [TP_060_040]
TP_VP5B  TP03-D  [TP_060_040]
TP_VP12  TP03-D  [TP_060_040]
TP_VP15  TP03-D  [TP_060_040]
TP_VP24  TP03-D  [TP_060_040]
UB5  25LC256-SOIC8  [SO8_206X127MM]
sheet S9999_HOLE
HOLE_CABLE3  DEBUGHOLE-15X15MM  [SLOT_NPTH_SQ15X15MM]
HOLE_CABLE4  DEBUGHOLE-15X15MM  [SLOT_NPTH_SQ15X15MM]
sheet T01.3680_DPS64_HDAV_H_P1
P1  HIGH-SIDE  [PG_3680_DPS64_HDAV_H_P1]  (sections A,B,C,D,E,F,G,H,I,J,K,L,M,N,O,P,Q,R,S,T,U,V,W,X,Y,Z)
sheet T02.3680_LPC_P2
P2  HIGH-SIDE  [PG_3680_HDRF3_LPC_P2]  (sections A,B,C,D,E,F,G,H,I,J,K,L,M,N,O,P,Q,R,S,T,U,V,W,X,Y,Z)
sheet T04.3680_DPS64_HDAV_H_P4
P4  HIGH-SIDE  [PG_3680_HDRF3_DPS32_P4]  (sections A,B,C,D,E,F,G,H,I,J,K,L,M,N,O,P,Q,R,S,T,U,V,W,X,Y,Z)
sheet T05.3680_LPC_P5
P5  HIGH-SIDE  [PG_3680_HDRF3_LPC_P5]  (sections A,B,C,D,E,F,G,H,I,J,K,L,M,N,O,P,Q,R,S,T,U,V,W,X,Y,Z)

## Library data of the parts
ATX_VD0V9 ATX_VD1V8 ATX_VD33 = HDR-8X2-M
BDB74-BDB77 BDB80-BDB83 BDB86 BDB87 = BD100-3A-SA
CB631 CB632 CB635 CB643 CB654 CB661 CB664 CB669 CB676 CB679 CB699 CB706 CB709 = 220U-10-T-SD
CB633 CB636 CB642 = 10U-10-T-SA-AVX
CB634 CB637 CB638 CB641 CB647 CB650 CB653 CB657 CB665 CB668 CB672 CB695 CB698 CB702 = 0.1U-10-X-S4-MU
CB639 CB648 = 10U-35-T-SC
CB640 CB649 = 47U-25-T-SD-AVX
CB651 CB666 CB696 = 3300P-50-X-S4
CB652 CB660 CB667 CB675 CB697 CB705 = CNC-S4
CB655 CB663 CB670 CB678 CB700 CB708 = 10U-10-X-S4
CB656 CB671 CB701 = 100P-50-N-S4
CB658 CB673 CB703 = 0.1U-16-X-S4-MU
CB659 CB674 CB704 = 100P-50-N-S4-MU
CB662 CB677 CB707 = 0.1U-16-X-S4
FUSEB1-FUSEB3 = MF-R185-40A-D
JB1 = ATX-10X2-MR
LB1 LB2 LB4 = L10U-3.6A-S10X10
LDB19 LDB20 LDB22 = LDR-2-S8
RB595 = 13K-1-S4
RB596 RB603 RB617 = 100K-0.1-S4
RB597 RB604 RB618 = 0-5-S4
RB598 RB605 RB619 = 10-1-S6
RB599 RB606 RB620 = 200K-10-D-Regulate
RB600 RB607 RB621 = 20K-1-S4
RB601 RB608 RB622 = 200-1-S4
RB623 RB627 = 7.15K-1-S4
RB624 RB628 = 9.1K-1-S4
SWB1 = SW-SLIDE-1-D4.7
UB70 UB71 UB73 = RT8293A-SOP8
VDD12_ATX = HDR-2X2-M
C524 C525 C528 C539 C548-C555 = 0.1U-50-X7R-S4-YA
C540-C547 = 0.1U-50-X-S6
R327 R338 R342 R346-R366 = 4.7K-0.1-S4-YA
U5-U16 = MAX4896ETP+-TQFN-EP-20
BD42-BD44 BD48 BD50-BD52 BD56-BD72 = BD120-3A-S8
CT2 CT4 CT6 = 10U-25-X7R-SA
CT3 CT5 CT7 = 4.7U-25-X7R-S8-TY
CT8 CT10 CT12 = 10U-50-X-SB-MU
CT9 CT11 CT13 = 4.7U-50-X-S8-MU
CT14 = 0.1U-16-X-S4-MU-1
LDB1-LDB6 = LDG-2-S8
LRB1 LRB2 = 330-1-S6
LRB3 = 1K-1-S6
LRB4 = 2K-1-S6
LRB5 LRB6 = 1.5K-1-S6
RB205 = 10K-1-S4
SCREW3 = CHROMA3680-OUTLINE-RF-TYPE2
TP_VN15 TP_VP5A TP_VP5B TP_VP12 TP_VP15 TP_VP24 = TP03-D
UB5 = 25LC256-SOIC8
HOLE_CABLE3 HOLE_CABLE4 = DEBUGHOLE-15X15MM
P1 P2 P4 P5 = HIGH-SIDE

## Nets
DGND: BD42.2 BD43.2 BD44.2 BD48.2 BD50.2 BD51.2 BD52.2 BD56.2 BD57.1 BD58.1 BD59.1 BD60.1 BD61.1 BD62.1 BD63.1 BD64.1 BD65.1 BD66.1 BD67.1 BD68.1 BD69.2 BD70.2 BD71.2 BD72.2 CB631.2 CB632.2 CB633.2 CB634.2 CB635.2 CB636.2 CB637.2 CB638.2 CB639.2 CB640.2 CB641.2 CB642.2 CB643.2 CB647.2 CB648.2 CB649.2 CB650.1 CB652.2 CB653.1 CB654.2 CB655.2 CB656.2 CB657.1 CB659.2 CB661.2 CB662.2 CB663.2 CB664.2 CB665.1 CB667.2 CB668.1 CB669.2 CB670.2 CB671.2 CB672.1 CB674.2 CB676.2 CB677.2 CB678.2 CB679.2 CB695.1 CB697.2 CB698.1 CB699.2 CB700.2 CB701.2 CB702.1 CB704.2 CB706.2 CB707.2 CB708.2 CB709.2 CT14.2 HOLE_CABLE3.G1 HOLE_CABLE3.G2 HOLE_CABLE3.G3 HOLE_CABLE3.G4 HOLE_CABLE3.G5 HOLE_CABLE3.G6 HOLE_CABLE3.G7 HOLE_CABLE3.G8 HOLE_CABLE3.G9 HOLE_CABLE3.G10 HOLE_CABLE3.G11 HOLE_CABLE3.G12 HOLE_CABLE3.G13 HOLE_CABLE3.G14 HOLE_CABLE3.G15 HOLE_CABLE3.G16 HOLE_CABLE3.G17 HOLE_CABLE3.G18 HOLE_CABLE3.G19 HOLE_CABLE3.G20 HOLE_CABLE3.G21 HOLE_CABLE3.G22 HOLE_CABLE3.G23 HOLE_CABLE3.G24 HOLE_CABLE3.G25 HOLE_CABLE3.G26 HOLE_CABLE3.G27 HOLE_CABLE3.G28 HOLE_CABLE3.G29 HOLE_CABLE3.G30 HOLE_CABLE3.G31 HOLE_CABLE3.G32 HOLE_CABLE3.G33 HOLE_CABLE3.G34 HOLE_CABLE3.G35 HOLE_CABLE3.G36 HOLE_CABLE3.G37 HOLE_CABLE3.G38 HOLE_CABLE3.G39 HOLE_CABLE3.G40 HOLE_CABLE3.G41 HOLE_CABLE3.G42 HOLE_CABLE3.G43 HOLE_CABLE3.G44 HOLE_CABLE3.G45 HOLE_CABLE3.G46 HOLE_CABLE3.G47 HOLE_CABLE3.G48 HOLE_CABLE3.G49 HOLE_CABLE3.G50 HOLE_CABLE3.G51 HOLE_CABLE3.G52 HOLE_CABLE3.G53 HOLE_CABLE3.G54 HOLE_CABLE3.G55 HOLE_CABLE3.G56 HOLE_CABLE3.G57 HOLE_CABLE3.G58 HOLE_CABLE3.G59 HOLE_CABLE3.G60 HOLE_CABLE3.G61 HOLE_CABLE3.G62 HOLE_CABLE3.G63 HOLE_CABLE3.G64 HOLE_CABLE3.G65 HOLE_CABLE3.G66 HOLE_CABLE3.G67 HOLE_CABLE3.G68 HOLE_CABLE4.G1 HOLE_CABLE4.G2 HOLE_CABLE4.G3 HOLE_CABLE4.G4 HOLE_CABLE4.G5 HOLE_CABLE4.G6 HOLE_CABLE4.G7 HOLE_CABLE4.G8 HOLE_CABLE4.G9 HOLE_CABLE4.G10 HOLE_CABLE4.G11 HOLE_CABLE4.G12 HOLE_CABLE4.G13 HOLE_CABLE4.G14 HOLE_CABLE4.G15 HOLE_CABLE4.G16 HOLE_CABLE4.G17 HOLE_CABLE4.G18 HOLE_CABLE4.G19 HOLE_CABLE4.G20 HOLE_CABLE4.G21 HOLE_CABLE4.G22 HOLE_CABLE4.G23 HOLE_CABLE4.G24 HOLE_CABLE4.G25 HOLE_CABLE4.G26 HOLE_CABLE4.G27 HOLE_CABLE4.G28 HOLE_CABLE4.G29 HOLE_CABLE4.G30 HOLE_CABLE4.G31 HOLE_CABLE4.G32 HOLE_CABLE4.G33 HOLE_CABLE4.G34 HOLE_CABLE4.G35 HOLE_CABLE4.G36 HOLE_CABLE4.G37 HOLE_CABLE4.G38 HOLE_CABLE4.G39 HOLE_CABLE4.G40 HOLE_CABLE4.G41 HOLE_CABLE4.G42 HOLE_CABLE4.G43 HOLE_CABLE4.G44 HOLE_CABLE4.G45 HOLE_CABLE4.G46 HOLE_CABLE4.G47 HOLE_CABLE4.G48 HOLE_CABLE4.G49 HOLE_CABLE4.G50 HOLE_CABLE4.G51 HOLE_CABLE4.G52 HOLE_CABLE4.G53 HOLE_CABLE4.G54 HOLE_CABLE4.G55 HOLE_CABLE4.G56 HOLE_CABLE4.G57 HOLE_CABLE4.G58 HOLE_CABLE4.G59 HOLE_CABLE4.G60 HOLE_CABLE4.G61 HOLE_CABLE4.G62 HOLE_CABLE4.G63 HOLE_CABLE4.G64 HOLE_CABLE4.G65 HOLE_CABLE4.G66 HOLE_CABLE4.G67 HOLE_CABLE4.G68 JB1.3(GND) JB1.5(GND(1)) JB1.7(GND(2)) JB1.13(GND(3)) JB1.15(GND(4)) JB1.16(GND(5)) JB1.17(GND(6)) LDB19.2(B) LDB20.2(B) LDB22.2(B) P2.A1(1) P2.A3(3) P2.A5(5) P2.A7(7) P2.A9(9) P2.A11(11) P2.B2(2) P2.B4(4) P2.B6(6) P2.B8(8) P2.B10(10) P2.B12(12) P2.C1(1) P2.C3(3) P2.C5(5) P2.C7(7) P2.C9(9) P2.C11(11) P2.D2(2) P2.D4(4) P2.D6(6) P2.D8(8) P2.D10(10) P2.D12(12) P2.E1(1) P2.E3(3) P2.E5(5) P2.E7(7) P2.E9(9) P2.E11(11) P2.F2(2) P2.F4(4) P2.F6(6) P2.F8(8) P2.F10(10) P2.F12(12) P2.G1(1) P2.G3(3) P2.G5(5) P2.G7(7) P2.G9(9) P2.G11(11) P2.H2(2) P2.H4(4) P2.H6(6) P2.H8(8) P2.H10(10) P2.H12(12) P2.I1(1) P2.I3(3) P2.I5(5) P2.I7(7) P2.I9(9) P2.I11(11) P2.J2(2) P2.J4(4) P2.J6(6) P2.J8(8) P2.J10(10) P2.J12(12) P2.K1(1) P2.K3(3) P2.K5(5) P2.K7(7) P2.K9(9) P2.K11(11) P2.L2(2) P2.L4(4) P2.L6(6) P2.L8(8) P2.L10(10) P2.L12(12) P2.M1(1) P2.M3(3) P2.M5(5) P2.M7(7) P2.M9(9) P2.M11(11) P2.N1(1) P2.N3(3) P2.N5(5) P2.N7(7) P2.N9(9) P2.N11(11) P2.O2(2) P2.O4(4) P2.O6(6) P2.O8(8) P2.O10(10) P2.O12(12) P2.P1(1) P2.P3(3) P2.P5(5) P2.P7(7) P2.P9(9) P2.P11(11) P2.Q2(2) P2.Q4(4) P2.Q6(6) P2.Q8(8) P2.Q10(10) P2.Q12(12) P2.R1(1) P2.R3(3) P2.R5(5) P2.R7(7) P2.R9(9) P2.R11(11) P2.S2(2) P2.S4(4) P2.S6(6) P2.S8(8) P2.S10(10) P2.S12(12) P2.T1(1) P2.T3(3) P2.T5(5) P2.T7(7) P2.T9(9) P2.T11(11) P2.U2(2) P2.U4(4) P2.U6(6) P2.U8(8) P2.U10(10) P2.U12(12) P2.V1(1) P2.V3(3) P2.V5(5) P2.V7(7) P2.V9(9) P2.V11(11) P2.W2(2) P2.W4(4) P2.W6(6) P2.W8(8) P2.W10(10) P2.W12(12) P2.X1(1) P2.X3(3) P2.X5(5) P2.X7(7) P2.X9(9) P2.X11(11) P2.Y2(2) P2.Y4(4) P2.Y6(6) P2.Y8(8) P2.Y10(10) P2.Y12(12) P2.Z1(1) P2.Z3(3) P2.Z5(5) P2.Z7(7) P2.Z9(9) P2.Z11(11) P5.A1(1) P5.A3(3) P5.A5(5) P5.A7(7) P5.A9(9) P5.A11(11) P5.B2(2) P5.B4(4) P5.B6(6) P5.B8(8) P5.B10(10) P5.B12(12) P5.C1(1) P5.C3(3) P5.C5(5) P5.C7(7) P5.C9(9) P5.C11(11) P5.D2(2) P5.D4(4) P5.D6(6) P5.D8(8) P5.D10(10) P5.D12(12) P5.E1(1) P5.E3(3) P5.E5(5) P5.E7(7) P5.E9(9) P5.E11(11) P5.F2(2) P5.F4(4) P5.F6(6) P5.F8(8) P5.F10(10) P5.F12(12) P5.G1(1) P5.G3(3) P5.G5(5) P5.G7(7) P5.G9(9) P5.G11(11) P5.H2(2) P5.H4(4) P5.H6(6) P5.H8(8) P5.H10(10) P5.H12(12) P5.I1(1) P5.I3(3) P5.I5(5) P5.I7(7) P5.I9(9) P5.I11(11) P5.J2(2) P5.J4(4) P5.J6(6) P5.J8(8) P5.J10(10) P5.J12(12) P5.K1(1) P5.K3(3) P5.K5(5) P5.K7(7) P5.K9(9) P5.K11(11) P5.L2(2) P5.L4(4) P5.L6(6) P5.L8(8) P5.L10(10) P5.L12(12) P5.M1(1) P5.M3(3) P5.M5(5) P5.M7(7) P5.M9(9) P5.M11(11) P5.N1(1) P5.N3(3) P5.N5(5) P5.N7(7) P5.N9(9) P5.N11(11) P5.O2(2) P5.O4(4) P5.O6(6) P5.O8(8) P5.O10(10) P5.O12(12) P5.P1(1) P5.P3(3) P5.P5(5) P5.P7(7) P5.P9(9) P5.P11(11) P5.Q2(2) P5.Q4(4) P5.Q6(6) P5.Q8(8) P5.Q10(10) P5.Q12(12) P5.R1(1) P5.R3(3) P5.R5(5) P5.R7(7) P5.R9(9) P5.R11(11) P5.S2(2) P5.S4(4) P5.S6(6) P5.S8(8) P5.S10(10) P5.S12(12) P5.T1(1) P5.T3(3) P5.T5(5) P5.T7(7) P5.T9(9) P5.T11(11) P5.U2(2) P5.U4(4) P5.U6(6) P5.U8(8) P5.U10(10) P5.U12(12) P5.V1(1) P5.V3(3) P5.V5(5) P5.V7(7) P5.V9(9) P5.V11(11) P5.W2(2) P5.W4(4) P5.W6(6) P5.W8(8) P5.W10(10) P5.W12(12) P5.X1(1) P5.X3(3) P5.X5(5) P5.X7(7) P5.X9(9) P5.X11(11) P5.Y2(2) P5.Y4(4) P5.Y6(6) P5.Y8(8) P5.Y10(10) P5.Y12(12) P5.Z1(1) P5.Z3(3) P5.Z5(5) P5.Z7(7) P5.Z9(9) P5.Z11(11) RB595.2 RB599.3 RB600.2 RB606.3 RB607.2 RB620.3 RB621.2 RB623.2 RB624.2 RB627.2 RB628.2 SWB1.3 UB70.4(GND) UB70.G1(EP) UB71.4(GND) UB71.G1(EP) UB73.4(GND) UB73.G1(EP) ; also on sheet 2 3 4 5 6 7 8 9 10 11 12 13 14 15 16 17 18 19 20 21 22 23 24 25 26 37 39
VDD5_ATX: BDB76.2 BDB77.2 BDB80.1 BDB82.1 BDB86.1 CB641.1 CB642.1 CB643.1 CB656.1 CB657.2 CB671.1 CB672.2 CB701.1 CB702.2
VDD12_ATX: BDB74.2 BDB75.2 CB647.1 CB648.1 CB649.1 VDD12_ATX.1 VDD12_ATX.3
VDD33_ATX: CB632.1 CB633.1 CB634.1 FUSEB1.2
AVO_GND: P1.N1(1) P1.N3(3) P1.N5(5) P1.N7(7) P1.N9(9) P1.N11(11) P1.O2(2) P1.O4(4) P1.O6(6) P1.O8(8) P1.O10(10) P1.O12(12) P1.P1(1) P1.P3(3) P1.P5(5) P1.P7(7) P1.P9(9) P1.P11(11) P1.Q2(2) P1.Q4(4) P1.Q6(6) P1.Q8(8) P1.Q10(10) P1.Q12(12) P1.R1(1) P1.R3(3) P1.R5(5) P1.R7(7) P1.R9(9) P1.R11(11) P1.S2(2) P1.S4(4) P1.S6(6) P1.S8(8) P1.S10(10) P1.S12(12) P1.T1(1) P1.T3(3) P1.T5(5) P1.T7(7) P1.T9(9) P1.T11(11) P1.U2(2) P1.U4(4) P1.U6(6) P1.U8(8) P1.U10(10) P1.U12(12) P1.V1(1) P1.V3(3) P1.V5(5) P1.V7(7) P1.V9(9) P1.V11(11) P1.W2(2) P1.W4(4) P1.W6(6) P1.W8(8) P1.W10(10) P1.W12(12) P1.X1(1) P1.X3(3) P1.X5(5) P1.X7(7) P1.X9(9) P1.X11(11) P1.Y2(2) P1.Y4(4) P1.Y6(6) P1.Y8(8) P1.Y10(10) P1.Y12(12) P1.Z1(1) P1.Z3(3) P1.Z5(5) P1.Z7(7) P1.Z9(9) P1.Z11(11) ; also on sheet 35 36 40
CAL_SPI_CK0: U5.4(SCLK) U6.4(SCLK) U7.4(SCLK) U8.4(SCLK) U9.4(SCLK) U10.4(SCLK) U11.4(SCLK) U12.4(SCLK) U13.4(SCLK) U14.4(SCLK) U15.4(SCLK) U16.4(SCLK) ; also on sheet 38
CAL_SPI_DIN0: U7.3(DIN) ; also on sheet 38
CAL_SPI_DO0: U16.5(DOUT) ; also on sheet 38
CAL_SPI_SL0: U5.2(~{CS}) U6.2(~{CS}) U7.2(~{CS}) U8.2(~{CS}) U9.2(~{CS}) U10.2(~{CS}) U11.2(~{CS}) U12.2(~{CS}) U13.2(~{CS}) U14.2(~{CS}) U15.2(~{CS}) U16.2(~{CS}) ; also on sheet 38
DPS_GND: BD57.2 BD58.2 BD59.2 BD60.2 BD61.2 BD62.2 BD63.2 BD64.2 BD65.2 BD66.2 BD67.2 BD68.2 P1.A1(1) P1.A5(5) P1.A9(9) P1.B4(4) P1.B8(8) P1.B12(12) P1.C1(1) P1.C5(5) P1.C9(9) P1.D4(4) P1.D8(8) P1.D12(12) P1.E1(1) P1.E5(5) P1.E9(9) P1.F4(4) P1.F8(8) P1.F12(12) P1.G1(1) P1.G5(5) P1.G9(9) P1.H4(4) P1.H8(8) P1.H12(12) P1.I1(1) P1.I5(5) P1.I9(9) P1.J4(4) P1.J8(8) P1.J12(12) P1.K1(1) P1.K5(5) P1.K9(9) P1.K11(11) P1.L2(2) P1.L4(4) P1.L6(6) P1.L8(8) P1.L10(10) P1.L12(12) P1.M1(1) P1.M3(3) P1.M5(5) P1.M7(7) P1.M9(9) P1.M11(11) P4.A1(1) P4.A5(5) P4.A9(9) P4.B4(4) P4.B8(8) P4.B12(12) P4.C1(1) P4.C5(5) P4.C9(9) P4.D4(4) P4.D8(8) P4.D12(12) P4.E1(1) P4.E5(5) P4.E9(9) P4.F4(4) P4.F8(8) P4.F12(12) P4.G1(1) P4.G5(5) P4.G9(9) P4.H4(4) P4.H8(8) P4.H12(12) P4.I1(1) P4.I5(5) P4.I9(9) P4.J4(4) P4.J8(8) P4.J12(12) P4.K1(1) P4.K5(5) P4.K9(9) P4.K11(11) P4.L2(2) P4.L4(4) P4.L6(6) P4.L8(8) P4.L10(10) P4.L12(12) P4.M1(1) P4.M3(3) P4.M5(5) P4.M7(7) P4.M9(9) P4.M11(11) P4.N1(1) P4.N3(3) P4.N5(5) P4.N7(7) P4.N9(9) P4.N11(11) P4.O2(2) P4.O4(4) P4.O6(6) P4.O8(8) P4.O10(10) P4.O12(12) P4.P1(1) P4.P3(3) P4.P5(5) P4.P7(7) P4.P9(9) P4.P11(11) P4.Q2(2) P4.Q4(4) P4.Q6(6) P4.Q8(8) P4.Q10(10) P4.Q12(12) P4.R1(1) P4.R3(3) P4.R5(5) P4.R7(7) P4.R9(9) P4.R11(11) P4.S2(2) P4.S4(4) P4.S6(6) P4.S8(8) P4.S10(10) P4.S12(12) P4.T1(1) P4.T3(3) P4.T5(5) P4.T7(7) P4.T9(9) P4.T11(11) P4.U2(2) P4.U4(4) P4.U6(6) P4.U8(8) P4.U10(10) P4.U12(12) P4.V1(1) P4.V3(3) P4.V5(5) P4.V7(7) P4.V9(9) P4.V11(11) P4.W2(2) P4.W4(4) P4.W6(6) P4.W8(8) P4.W10(10) P4.W12(12) P4.X1(1) P4.X3(3) P4.X5(5) P4.X7(7) P4.X9(9) P4.X11(11) P4.Y2(2) P4.Y4(4) P4.Y6(6) P4.Y8(8) P4.Y10(10) P4.Y12(12) P4.Z1(1) P4.Z3(3) P4.Z5(5) P4.Z7(7) P4.Z9(9) P4.Z11(11) ; also on sheet 35 36 40
IDCE1: UB5.1(~{CS}) ; also on sheet 38
IDDI: UB5.5(SI) ; also on sheet 38
IDDO: UB5.2(SO) ; also on sheet 38
IDSK: UB5.6(SCK) ; also on sheet 38
LB_GND: BD42.1 BD43.1 BD44.1 BD48.1 BD50.1 BD51.1 BD52.1 BD56.1 BD69.1 BD70.1 BD71.1 BD72.1 C524.2 C525.2 C528.2 C539.2 C540.2 C541.2 C542.2 C543.2 C544.2 C545.2 C546.2 C547.2 C548.2 C549.2 C550.2 C551.2 C552.2 C553.2 C554.2 C555.2 CT2.2 CT3.2 CT4.2 CT5.2 CT6.2 CT7.2 CT8.2 CT9.2 CT10.2 CT11.2 CT12.2 CT13.2 LDB1.2(B) LDB2.2(B) LDB3.2(B) LDB4.2(B) LDB5.2(B) LRB6.2 U5.7(SPLD) U5.10(PGND[1]) U5.13(GND) U5.16(PGND[2]) U5.EP(EP(GND)) U6.7(SPLD) U6.10(PGND[1]) U6.13(GND) U6.16(PGND[2]) U6.EP(EP(GND)) U7.7(SPLD) U7.10(PGND[1]) U7.13(GND) U7.16(PGND[2]) U7.EP(EP(GND)) U8.7(SPLD) U8.10(PGND[1]) U8.13(GND) U8.16(PGND[2]) U8.EP(EP(GND)) U9.7(SPLD) U9.10(PGND[1]) U9.13(GND) U9.16(PGND[2]) U9.EP(EP(GND)) U10.7(SPLD) U10.10(PGND[1]) U10.13(GND) U10.16(PGND[2]) U10.EP(EP(GND)) U11.7(SPLD) U11.10(PGND[1]) U11.13(GND) U11.16(PGND[2]) U11.EP(EP(GND)) U12.7(SPLD) U12.10(PGND[1]) U12.13(GND) U12.16(PGND[2]) U12.EP(EP(GND)) U13.7(SPLD) U13.10(PGND[1]) U13.13(GND) U13.16(PGND[2]) U13.EP(EP(GND)) U14.7(SPLD) U14.10(PGND[1]) U14.13(GND) U14.16(PGND[2]) U14.EP(EP(GND)) U15.7(SPLD) U15.10(PGND[1]) U15.13(GND) U15.16(PGND[2]) U15.EP(EP(GND)) U16.7(SPLD) U16.10(PGND[1]) U16.13(GND) U16.16(PGND[2]) U16.EP(EP(GND)) UB5.4(VSS) ; also on sheet 38
S0_ATX_VD0V9: ATX_VD0V9.2 ; also on sheet 4
S0_ATX_VD1V8: ATX_VD1V8.2 ; also on sheet 4
S0_ATX_VD33: ATX_VD33.2 ; also on sheet 4
S0_LPC_CH00: P2.N2(2)
S0_LPC_CH01: P2.N4(4)
S0_LPC_CH02: P2.N6(6)
S0_LPC_CH03: P2.N8(8)
S0_LPC_CH04: P2.N10(10)
S0_LPC_CH05: P2.N12(12)
S0_LPC_CH06: P2.O1(1)
S0_LPC_CH07: P2.O3(3)
S0_LPC_CH08: P2.O5(5)
S0_LPC_CH09: P2.O7(7)
S0_LPC_CH10: P2.O9(9)
S0_LPC_CH11: P2.O11(11)
S0_LPC_CH12: P2.P2(2)
S0_LPC_CH13: P2.P4(4)
S0_LPC_CH14: P2.P6(6)
S0_LPC_CH15: P2.P8(8)
S0_LPC_CH16: P2.P10(10)
S0_LPC_CH17: P2.P12(12)
S0_LPC_CH18: P2.Q1(1)
S0_LPC_CH19: P2.Q3(3)
S0_LPC_CH20: P2.Q5(5)
S0_LPC_CH21: P2.Q7(7)
S0_LPC_CH22: P2.Q9(9)
S0_LPC_CH23: P2.Q11(11)
S0_LPC_CH24: P2.R2(2)
S0_LPC_CH25: P2.R4(4)
S0_LPC_CH26: P2.R6(6)
S0_LPC_CH27: P2.R8(8)
S0_LPC_CH28: P2.R10(10)
S0_LPC_CH29: P2.R12(12)
S0_LPC_CH30: P2.S1(1)
S0_LPC_CH31: P2.S3(3)
S0_LPC_CH64: P2.S5(5)
S0_LPC_CH65: P2.S7(7)
S0_LPC_CH66: P2.S9(9)
S0_LPC_CH67: P2.S11(11)
S0_LPC_CH68: P2.T2(2)
S0_LPC_CH69: P2.T4(4)
S0_LPC_CH70: P2.T6(6)
S0_LPC_CH71: P2.T8(8)
S0_LPC_CH72: P2.T10(10)
S0_LPC_CH73: P2.T12(12)
S0_LPC_CH74: P2.U1(1)
S0_LPC_CH75: P2.U3(3)
S0_LPC_CH76: P2.U5(5)
S0_LPC_CH77: P2.U7(7)
S0_LPC_CH78: P2.U9(9)
S0_LPC_CH79: P2.U11(11)
S0_LPC_CH80: P2.V2(2)
S0_LPC_CH81: P2.V4(4)
S0_LPC_CH82: P2.V6(6)
S0_LPC_CH83: P2.V8(8)
S0_LPC_CH84: P2.V10(10)
S0_LPC_CH85: P2.V12(12)
S0_LPC_CH86: P2.W1(1)
S0_LPC_CH87: P2.W3(3)
S0_LPC_CH88: P2.W5(5)
S0_LPC_CH89: P2.W7(7)
S0_LPC_CH90: P2.W9(9)
S0_LPC_CH91: P2.W11(11)
S0_LPC_CH92: P2.X2(2)
S0_LPC_CH93: P2.X4(4)
S0_LPC_CH94: P2.X6(6)
S0_LPC_CH95: P2.X8(8)
S0_LPC_DGS64: P2.X12(12)
S0_LPC_UB9: P2.Y5(5)
S0_LPC_UB10: P2.Z6(6)
S0_LPC_UB11: P2.Y7(7)
S0_LPC_UB12: P2.Z8(8)
S0_LPC_UB13: P2.Y9(9)
S0_LPC_UB14: P2.Z10(10)
S0_LPC_UB15: P2.Y11(11)
S0_PMU0_F: P2.Y1(1)
S0_PMU0_G: P2.Y3(3)
S0_PMU0_S: P2.Z2(2)
S1_ATX_VD0V9: ATX_VD0V9.4 ; also on sheet 7
S1_ATX_VD1V8: ATX_VD1V8.4 ; also on sheet 7
S1_ATX_VD33: ATX_VD33.4 ; also on sheet 7
S1_LPC_CH00: P5.A2(2)
S1_LPC_CH01: P5.A4(4)
S1_LPC_CH02: P5.A6(6)
S1_LPC_CH03: P5.A8(8)
S1_LPC_CH04: P5.A10(10)
S1_LPC_CH05: P5.A12(12)
S1_LPC_CH06: P5.B1(1)
S1_LPC_CH07: P5.B3(3)
S1_LPC_CH08: P5.B5(5)
S1_LPC_CH09: P5.B7(7)
S1_LPC_CH10: P5.B9(9)
S1_LPC_CH11: P5.B11(11)
S1_LPC_CH12: P5.C2(2)
S1_LPC_CH13: P5.C4(4)
S1_LPC_CH14: P5.C6(6)
S1_LPC_CH15: P5.C8(8)
S1_LPC_CH16: P5.C10(10)
S1_LPC_CH17: P5.C12(12)
S1_LPC_CH18: P5.D1(1)
S1_LPC_CH19: P5.D3(3)
S1_LPC_CH20: P5.D5(5)
S1_LPC_CH21: P5.D7(7)
S1_LPC_CH22: P5.D9(9)
S1_LPC_CH23: P5.D11(11)
S1_LPC_CH24: P5.E2(2)
S1_LPC_CH25: P5.E4(4)
S1_LPC_CH26: P5.E6(6)
S1_LPC_CH27: P5.E8(8)
S1_LPC_CH28: P5.E10(10)
S1_LPC_CH29: P5.E12(12)
S1_LPC_CH30: P5.F1(1)
S1_LPC_CH31: P5.F3(3)
S1_LPC_CH64: P5.F5(5)
S1_LPC_CH65: P5.F7(7)
S1_LPC_CH66: P5.F9(9)
S1_LPC_CH67: P5.F11(11)
S1_LPC_CH68: P5.G2(2)
S1_LPC_CH69: P5.G4(4)
S1_LPC_CH70: P5.G6(6)
S1_LPC_CH71: P5.G8(8)
S1_LPC_CH72: P5.G10(10)
S1_LPC_CH73: P5.G12(12)
S1_LPC_CH74: P5.H1(1)
S1_LPC_CH75: P5.H3(3)
S1_LPC_CH76: P5.H5(5)
S1_LPC_CH77: P5.H7(7)
S1_LPC_CH78: P5.H9(9)
S1_LPC_CH79: P5.H11(11)
S1_LPC_CH80: P5.I2(2)
S1_LPC_CH81: P5.I4(4)
S1_LPC_CH82: P5.I6(6)
S1_LPC_CH83: P5.I8(8)
S1_LPC_CH84: P5.I10(10)
S1_LPC_CH85: P5.I12(12)
S1_LPC_CH86: P5.J1(1)
S1_LPC_CH87: P5.J3(3)
S1_LPC_CH88: P5.J5(5)
S1_LPC_CH89: P5.J7(7)
S1_LPC_CH90: P5.J9(9)
S1_LPC_CH91: P5.J11(11)
S1_LPC_CH92: P5.K2(2)
S1_LPC_CH93: P5.K4(4)
S1_LPC_CH94: P5.K6(6)
S1_LPC_CH95: P5.K8(8)
S1_LPC_DGS64: P5.K12(12)
S1_LPC_UB9: P5.L5(5)
S1_LPC_UB10: P5.M6(6)
S1_LPC_UB11: P5.L7(7)
S1_LPC_UB12: P5.M8(8)
S1_LPC_UB13: P5.L9(9)
S1_LPC_UB14: P5.M10(10)
S1_LPC_UB15: P5.L11(11)
S1_PMU0_F: P5.L1(1)
S1_PMU0_G: P5.L3(3)
S1_PMU0_S: P5.M2(2)
S2_ATX_VD0V9: ATX_VD0V9.6 ; also on sheet 10
S2_ATX_VD1V8: ATX_VD1V8.6 ; also on sheet 10
S2_ATX_VD33: ATX_VD33.6 ; also on sheet 10
S2_LPC_CH00: P2.A2(2)
S2_LPC_CH01: P2.A4(4)
S2_LPC_CH02: P2.A6(6)
S2_LPC_CH03: P2.A8(8)
S2_LPC_CH04: P2.A10(10)
S2_LPC_CH05: P2.A12(12)
S2_LPC_CH06: P2.B1(1)
S2_LPC_CH07: P2.B3(3)
S2_LPC_CH08: P2.B5(5)
S2_LPC_CH09: P2.B7(7)
S2_LPC_CH10: P2.B9(9)
S2_LPC_CH11: P2.B11(11)
S2_LPC_CH12: P2.C2(2)
S2_LPC_CH13: P2.C4(4)
S2_LPC_CH14: P2.C6(6)
S2_LPC_CH15: P2.C8(8)
S2_LPC_CH16: P2.C10(10)
S2_LPC_CH17: P2.C12(12)
S2_LPC_CH18: P2.D1(1)
S2_LPC_CH19: P2.D3(3)
S2_LPC_CH20: P2.D5(5)
S2_LPC_CH21: P2.D7(7)
S2_LPC_CH22: P2.D9(9)
S2_LPC_CH23: P2.D11(11)
S2_LPC_CH24: P2.E2(2)
S2_LPC_CH25: P2.E4(4)
S2_LPC_CH26: P2.E6(6)
S2_LPC_CH27: P2.E8(8)
S2_LPC_CH28: P2.E10(10)
S2_LPC_CH29: P2.E12(12)
S2_LPC_CH30: P2.F1(1)
S2_LPC_CH31: P2.F3(3)
S2_LPC_CH64: P2.F5(5)
S2_LPC_CH65: P2.F7(7)
S2_LPC_CH66: P2.F9(9)
S2_LPC_CH67: P2.F11(11)
S2_LPC_CH68: P2.G2(2)
S2_LPC_CH69: P2.G4(4)
S2_LPC_CH70: P2.G6(6)
S2_LPC_CH71: P2.G8(8)
S2_LPC_CH72: P2.G10(10)
S2_LPC_CH73: P2.G12(12)
S2_LPC_CH74: P2.H1(1)
S2_LPC_CH75: P2.H3(3)
S2_LPC_CH76: P2.H5(5)
S2_LPC_CH77: P2.H7(7)
S2_LPC_CH78: P2.H9(9)
S2_LPC_CH79: P2.H11(11)
S2_LPC_CH80: P2.I2(2)
S2_LPC_CH81: P2.I4(4)
S2_LPC_CH82: P2.I6(6)
S2_LPC_CH83: P2.I8(8)
S2_LPC_CH84: P2.I10(10)
S2_LPC_CH85: P2.I12(12)
S2_LPC_CH86: P2.J1(1)
S2_LPC_CH87: P2.J3(3)
S2_LPC_CH88: P2.J5(5)
S2_LPC_CH89: P2.J7(7)
S2_LPC_CH90: P2.J9(9)
S2_LPC_CH91: P2.J11(11)
S2_LPC_CH92: P2.K2(2)
S2_LPC_CH93: P2.K4(4)
S2_LPC_CH94: P2.K6(6)
S2_LPC_CH95: P2.K8(8)
S2_LPC_DGS64: P2.K12(12)
S2_LPC_UB9: P2.L5(5)
S2_LPC_UB10: P2.M6(6)
S2_LPC_UB11: P2.L7(7)
S2_LPC_UB12: P2.M8(8)
S2_LPC_UB13: P2.L9(9)
S2_LPC_UB14: P2.M10(10)
S2_LPC_UB15: P2.L11(11)
S2_PMU0_F: P2.L1(1)
S2_PMU0_G: P2.L3(3)
S2_PMU0_S: P2.M2(2)
S3_ATX_VD0V9: ATX_VD0V9.8 ; also on sheet 13
S3_ATX_VD1V8: ATX_VD1V8.8 ; also on sheet 13
S3_ATX_VD33: ATX_VD33.8 ; also on sheet 13
S3_LPC_CH00: P5.N2(2)
S3_LPC_CH01: P5.N4(4)
S3_LPC_CH02: P5.N6(6)
S3_LPC_CH03: P5.N8(8)
S3_LPC_CH04: P5.N10(10)
S3_LPC_CH05: P5.N12(12)
S3_LPC_CH06: P5.O1(1)
S3_LPC_CH07: P5.O3(3)
S3_LPC_CH08: P5.O5(5)
S3_LPC_CH09: P5.O7(7)
S3_LPC_CH10: P5.O9(9)
S3_LPC_CH11: P5.O11(11)
S3_LPC_CH12: P5.P2(2)
S3_LPC_CH13: P5.P4(4)
S3_LPC_CH14: P5.P6(6)
S3_LPC_CH15: P5.P8(8)
S3_LPC_CH16: P5.P10(10)
S3_LPC_CH17: P5.P12(12)
S3_LPC_CH18: P5.Q1(1)
S3_LPC_CH19: P5.Q3(3)
S3_LPC_CH20: P5.Q5(5)
S3_LPC_CH21: P5.Q7(7)
S3_LPC_CH22: P5.Q9(9)
S3_LPC_CH23: P5.Q11(11)
S3_LPC_CH24: P5.R2(2)
S3_LPC_CH25: P5.R4(4)
S3_LPC_CH26: P5.R6(6)
S3_LPC_CH27: P5.R8(8)
S3_LPC_CH28: P5.R10(10)
S3_LPC_CH29: P5.R12(12)
S3_LPC_CH30: P5.S1(1)
S3_LPC_CH31: P5.S3(3)
S3_LPC_CH64: P5.S5(5)
S3_LPC_CH65: P5.S7(7)
S3_LPC_CH66: P5.S9(9)
S3_LPC_CH67: P5.S11(11)
S3_LPC_CH68: P5.T2(2)
S3_LPC_CH69: P5.T4(4)
S3_LPC_CH70: P5.T6(6)
S3_LPC_CH71: P5.T8(8)
S3_LPC_CH72: P5.T10(10)
S3_LPC_CH73: P5.T12(12)
S3_LPC_CH74: P5.U1(1)
S3_LPC_CH75: P5.U3(3)
S3_LPC_CH76: P5.U5(5)
S3_LPC_CH77: P5.U7(7)
S3_LPC_CH78: P5.U9(9)
S3_LPC_CH79: P5.U11(11)
S3_LPC_CH80: P5.V2(2)
S3_LPC_CH81: P5.V4(4)
S3_LPC_CH82: P5.V6(6)
S3_LPC_CH83: P5.V8(8)
S3_LPC_CH84: P5.V10(10)
S3_LPC_CH85: P5.V12(12)
S3_LPC_CH86: P5.W1(1)
S3_LPC_CH87: P5.W3(3)
S3_LPC_CH88: P5.W5(5)
S3_LPC_CH89: P5.W7(7)
S3_LPC_CH90: P5.W9(9)
S3_LPC_CH91: P5.W11(11)
S3_LPC_CH92: P5.X2(2)
S3_LPC_CH93: P5.X4(4)
S3_LPC_CH94: P5.X6(6)
S3_LPC_CH95: P5.X8(8)
S3_LPC_DGS64: P5.X12(12)
S3_LPC_UB9: P5.Y5(5)
S3_LPC_UB10: P5.Z6(6)
S3_LPC_UB11: P5.Y7(7)
S3_LPC_UB12: P5.Z8(8)
S3_LPC_UB13: P5.Y9(9)
S3_LPC_UB14: P5.Z10(10)
S3_LPC_UB15: P5.Y11(11)
S3_PMU0_F: P5.Y1(1)
S3_PMU0_G: P5.Y3(3)
S3_PMU0_S: P5.Z2(2)
S4_ATX_VD0V9: ATX_VD0V9.10 ; also on sheet 16
S4_ATX_VD1V8: ATX_VD1V8.10 ; also on sheet 16
S4_ATX_VD33: ATX_VD33.10 ; also on sheet 16
S5_ATX_VD0V9: ATX_VD0V9.12 ; also on sheet 19
S5_ATX_VD1V8: ATX_VD1V8.12 ; also on sheet 19
S5_ATX_VD33: ATX_VD33.12 ; also on sheet 19
S6_ATX_VD0V9: ATX_VD0V9.14 ; also on sheet 22
S6_ATX_VD1V8: ATX_VD1V8.14 ; also on sheet 22
S6_ATX_VD33: ATX_VD33.14 ; also on sheet 22
S7_ATX_VD0V9: ATX_VD0V9.16 ; also on sheet 25
S7_ATX_VD1V8: ATX_VD1V8.16 ; also on sheet 25
S7_ATX_VD33: ATX_VD33.16 ; also on sheet 25
S8_AVO_DGS02: P1.P12(12)
S8_AVO_DGS03: P1.P6(6)
S8_CAP06_N: P1.O9(9)
S8_CAP06_NSH: P1.O11(11)
S8_CAP06_P: P1.N10(10)
S8_CAP06_PSH: P1.N8(8)
S8_CAP07_N: P1.O3(3)
S8_CAP07_NSH: P1.O5(5)
S8_CAP07_P: P1.N4(4)
S8_CAP07_PSH: P1.N2(2)
S8_CAP14_N: P1.W9(9)
S8_CAP14_NSH: P1.W11(11)
S8_CAP14_P: P1.V10(10)
S8_CAP14_PSH: P1.V8(8)
S8_CAP15_N: P1.W3(3)
S8_CAP15_NSH: P1.W5(5)
S8_CAP15_P: P1.V4(4)
S8_CAP15_PSH: P1.V2(2)
S8_REF08_F: P1.T8(8)
S8_REF08_S: P1.U7(7)
S8_REF09_F: P1.T6(6)
S8_REF09_S: P1.U5(5)
S8_REF10_F: P1.T4(4)
S8_REF10_S: P1.U3(3)
S8_REF11_F: P1.T2(2)
S8_REF11_S: P1.U1(1)
S8_REF12_F: P1.R8(8)
S8_REF12_S: P1.S7(7)
S8_REF13_F: P1.R6(6)
S8_REF13_S: P1.S5(5)
S8_REF14_F: P1.R4(4)
S8_REF14_S: P1.S3(3)
S8_REF15_F: P1.R2(2)
S8_REF15_S: P1.S1(1)
S8_SRC02_N: P1.Q9(9)
S8_SRC02_NSH: P1.Q11(11)
S8_SRC02_P: P1.P10(10)
S8_SRC02_PSH: P1.P8(8)
S8_SRC03_N: P1.Q3(3)
S8_SRC03_NSH: P1.Q5(5)
S8_SRC03_P: P1.P4(4)
S8_SRC03_PSH: P1.P2(2)
S8_SRC10_N: P1.Y9(9)
S8_SRC10_NSH: P1.Y11(11)
S8_SRC10_P: P1.X10(10)
S8_SRC10_PSH: P1.X8(8)
S8_SRC11_N: P1.Y3(3)
S8_SRC11_NSH: P1.Y5(5)
S8_SRC11_P: P1.X4(4)
S8_SRC11_PSH: P1.X2(2)
S10_DPS_DGS00: P1.A3(3)
S10_DPS_DGS01: P1.A7(7)
S10_DPS_DGS02: P1.A11(11)
S10_DPS_DGS03: P1.B2(2)
S10_DPS_DGS04: P1.B6(6)
S10_DPS_DGS05: P1.B10(10)
S10_DPS_DGS06: P1.C3(3)
S10_DPS_DGS07: P1.C7(7)
S10_DPS_DGS08: P1.C11(11)
S10_DPS_DGS09: P1.D2(2)
S10_DPS_DGS10: P1.D6(6)
S10_DPS_DGS11: P1.D10(10)
S10_DPS_DGS12: P1.E3(3)
S10_DPS_DGS13: P1.E7(7)
S10_DPS_DGS14: P1.E11(11)
S10_DPS_DGS15: P1.F2(2)
S10_DPS_DGS16: P1.F6(6)
S10_DPS_DGS17: P1.F10(10)
S10_DPS_DGS18: P1.G3(3)
S10_DPS_DGS19: P1.G7(7)
S10_DPS_DGS20: P1.G11(11)
S10_DPS_DGS21: P1.H2(2)
S10_DPS_DGS22: P1.H6(6)
S10_DPS_DGS23: P1.H10(10)
S10_DPS_DGS24: P1.I3(3)
S10_DPS_DGS25: P1.I7(7)
S10_DPS_DGS26: P1.I11(11)
S10_DPS_DGS27: P1.J2(2)
S10_DPS_DGS28: P1.J6(6)
S10_DPS_DGS29: P1.J10(10)
S10_DPS_DGS30: P1.K3(3)
S10_DPS_DGS31: P1.K7(7)
S10_DPS_F00: P1.A2(2)
S10_DPS_F01: P1.A6(6)
S10_DPS_F02: P1.A10(10)
S10_DPS_F03: P1.B1(1)
S10_DPS_F04: P1.B5(5)
S10_DPS_F05: P1.B9(9)
S10_DPS_F06: P1.C2(2)
S10_DPS_F07: P1.C6(6)
S10_DPS_F08: P1.C10(10)
S10_DPS_F09: P1.D1(1)
S10_DPS_F10: P1.D5(5)
S10_DPS_F11: P1.D9(9)
S10_DPS_F12: P1.E2(2)
S10_DPS_F13: P1.E6(6)
S10_DPS_F14: P1.E10(10)
S10_DPS_F15: P1.F1(1)
S10_DPS_F16: P1.F5(5)
S10_DPS_F17: P1.F9(9)
S10_DPS_F18: P1.G2(2)
S10_DPS_F19: P1.G6(6)
S10_DPS_F20: P1.G10(10)
S10_DPS_F21: P1.H1(1)
S10_DPS_F22: P1.H5(5)
S10_DPS_F23: P1.H9(9)
S10_DPS_F24: P1.I2(2)
S10_DPS_F25: P1.I6(6)
S10_DPS_F26: P1.I10(10)
S10_DPS_F27: P1.J1(1)
S10_DPS_F28: P1.J5(5)
S10_DPS_F29: P1.J9(9)
S10_DPS_F30: P1.K2(2)
S10_DPS_F31: P1.K6(6)
S10_DPS_S00: P1.A4(4)
S10_DPS_S01: P1.A8(8)
S10_DPS_S02: P1.A12(12)
S10_DPS_S03: P1.B3(3)
S10_DPS_S04: P1.B7(7)
S10_DPS_S05: P1.B11(11)
S10_DPS_S06: P1.C4(4)
S10_DPS_S07: P1.C8(8)
S10_DPS_S08: P1.C12(12)
S10_DPS_S09: P1.D3(3)
S10_DPS_S10: P1.D7(7)
S10_DPS_S11: P1.D11(11)
S10_DPS_S12: P1.E4(4)
S10_DPS_S13: P1.E8(8)
S10_DPS_S14: P1.E12(12)
S10_DPS_S15: P1.F3(3)
S10_DPS_S16: P1.F7(7)
S10_DPS_S17: P1.F11(11)
S10_DPS_S18: P1.G4(4)
S10_DPS_S19: P1.G8(8)
S10_DPS_S20: P1.G12(12)
S10_DPS_S21: P1.H3(3)
S10_DPS_S22: P1.H7(7)
S10_DPS_S23: P1.H11(11)
S10_DPS_S24: P1.I4(4)
S10_DPS_S25: P1.I8(8)
S10_DPS_S26: P1.I12(12)
S10_DPS_S27: P1.J3(3)
S10_DPS_S28: P1.J7(7)
S10_DPS_S29: P1.J11(11)
S10_DPS_S30: P1.K4(4)
S10_DPS_S31: P1.K8(8)
S10_DPS_UB1: P1.L5(5)
S10_DPS_UB2: P1.M6(6)
S10_DPS_UB3: P1.L7(7)
S10_DPS_UB4: P1.M8(8)
S10_DPS_UB5: P1.L9(9)
S10_DPS_UB6: P1.M10(10)
S10_DPS_UB7: P1.L11(11)
S23_DPS_DGS00: P4.A3(3)
S23_DPS_DGS01: P4.A7(7)
S23_DPS_DGS02: P4.A11(11)
S23_DPS_DGS03: P4.B2(2)
S23_DPS_DGS04: P4.B6(6)
S23_DPS_DGS05: P4.B10(10)
S23_DPS_DGS06: P4.C3(3)
S23_DPS_DGS07: P4.C7(7)
S23_DPS_DGS08: P4.C11(11)
S23_DPS_DGS09: P4.D2(2)
S23_DPS_DGS10: P4.D6(6)
S23_DPS_DGS11: P4.D10(10)
S23_DPS_DGS12: P4.E3(3)
S23_DPS_DGS13: P4.E7(7)
S23_DPS_DGS14: P4.E11(11)
S23_DPS_DGS15: P4.F2(2)
S23_DPS_DGS16: P4.F6(6)
S23_DPS_DGS17: P4.F10(10)
S23_DPS_DGS18: P4.G3(3)
S23_DPS_DGS19: P4.G7(7)
S23_DPS_DGS20: P4.G11(11)
S23_DPS_DGS21: P4.H2(2)
S23_DPS_DGS22: P4.H6(6)
S23_DPS_DGS23: P4.H10(10)
S23_DPS_DGS24: P4.I3(3)
S23_DPS_DGS25: P4.I7(7)
S23_DPS_DGS26: P4.I11(11)
S23_DPS_DGS27: P4.J2(2)
S23_DPS_DGS28: P4.J6(6)
S23_DPS_DGS29: P4.J10(10)
S23_DPS_DGS30: P4.K3(3)
S23_DPS_DGS31: P4.K7(7)
S23_DPS_F00: P4.A2(2)
S23_DPS_F01: P4.A6(6)
S23_DPS_F02: P4.A10(10)
S23_DPS_F03: P4.B1(1)
S23_DPS_F04: P4.B5(5)
S23_DPS_F05: P4.B9(9)
S23_DPS_F06: P4.C2(2)
S23_DPS_F07: P4.C6(6)
S23_DPS_F08: P4.C10(10)
S23_DPS_F09: P4.D1(1)
S23_DPS_F10: P4.D5(5)
S23_DPS_F11: P4.D9(9)
S23_DPS_F12: P4.E2(2)
S23_DPS_F13: P4.E6(6)
S23_DPS_F14: P4.E10(10)
S23_DPS_F15: P4.F1(1)
S23_DPS_F16: P4.F5(5)
S23_DPS_F17: P4.F9(9)
S23_DPS_F18: P4.G2(2)
S23_DPS_F19: P4.G6(6)
S23_DPS_F20: P4.G10(10)
S23_DPS_F21: P4.H1(1)
S23_DPS_F22: P4.H5(5)
S23_DPS_F23: P4.H9(9)
S23_DPS_F24: P4.I2(2)
S23_DPS_F25: P4.I6(6)
S23_DPS_F26: P4.I10(10)
S23_DPS_F27: P4.J1(1)
S23_DPS_F28: P4.J5(5)
S23_DPS_F29: P4.J9(9)
S23_DPS_F30: P4.K2(2)
S23_DPS_F31: P4.K6(6)
S23_DPS_S00: P4.A4(4)
S23_DPS_S01: P4.A8(8)
S23_DPS_S02: P4.A12(12)
S23_DPS_S03: P4.B3(3)
S23_DPS_S04: P4.B7(7)
S23_DPS_S05: P4.B11(11)
S23_DPS_S06: P4.C4(4)
S23_DPS_S07: P4.C8(8)
S23_DPS_S08: P4.C12(12)
S23_DPS_S09: P4.D3(3)
S23_DPS_S10: P4.D7(7)
S23_DPS_S11: P4.D11(11)
S23_DPS_S12: P4.E4(4)
S23_DPS_S13: P4.E8(8)
S23_DPS_S14: P4.E12(12)
S23_DPS_S15: P4.F3(3)
S23_DPS_S16: P4.F7(7)
S23_DPS_S17: P4.F11(11)
S23_DPS_S18: P4.G4(4)
S23_DPS_S19: P4.G8(8)
S23_DPS_S20: P4.G12(12)
S23_DPS_S21: P4.H3(3)
S23_DPS_S22: P4.H7(7)
S23_DPS_S23: P4.H11(11)
S23_DPS_S24: P4.I4(4)
S23_DPS_S25: P4.I8(8)
S23_DPS_S26: P4.I12(12)
S23_DPS_S27: P4.J3(3)
S23_DPS_S28: P4.J7(7)
S23_DPS_S29: P4.J11(11)
S23_DPS_S30: P4.K4(4)
S23_DPS_S31: P4.K8(8)
SC_1_ATX_5V_SRC: BDB76.1 BDB77.1 CB635.1 CB636.1 CB637.1 FUSEB2.2
SC_1_ATX_12V_SRC: BDB74.1 BDB75.1 CB638.1 CB639.1 CB640.1 FUSEB3.2
SC_ATX_3V3_SRC: CB631.1 FUSEB1.1 JB1.1(+3.3V(1)) JB1.2(+3.3V(2)) JB1.11(+3.3V(3))
SC_ATX_5V_SRC: FUSEB2.1 JB1.4(+5V(1)) JB1.6(+5V(2)) JB1.19(+5V(3)) JB1.20(+5V(4))
SC_ATX_12V_SRC: FUSEB3.1 JB1.10(+12V)
SC_ATX_POWER_ON: JB1.14(Power_On) SWB1.2
SC_ATX_VD0V9_COM: ATX_VD0V9.1 ATX_VD0V9.3 ATX_VD0V9.5 ATX_VD0V9.7 ATX_VD0V9.9 ATX_VD0V9.11 ATX_VD0V9.13 ATX_VD0V9.15 BDB87.2 CB709.1
SC_ATX_VD0V9_LED: LDB22.1(A) RB622.2
SC_ATX_VD0V9_SW: CB703.2 LB4.1 RB619.1 UB73.3(SW)
SC_ATX_VD0V9_VOUT: BDB87.1 CB705.1 CB706.1 CB707.1 CB708.1 LB4.2 RB620.2 RB622.1
SC_ATX_VD1V8_COM: ATX_VD1V8.1 ATX_VD1V8.3 ATX_VD1V8.5 ATX_VD1V8.7 ATX_VD1V8.9 ATX_VD1V8.11 ATX_VD1V8.13 ATX_VD1V8.15 BDB83.2 CB679.1
SC_ATX_VD1V8_LED: LDB20.1(A) RB608.2
SC_ATX_VD1V8_SW: CB673.2 LB2.1 RB605.1 UB71.3(SW)
SC_ATX_VD1V8_VOUT: BDB83.1 CB675.1 CB676.1 CB677.1 CB678.1 LB2.2 RB606.2 RB608.1
SC_ATX_VD33_COM: ATX_VD33.1 ATX_VD33.3 ATX_VD33.5 ATX_VD33.7 ATX_VD33.9 ATX_VD33.11 ATX_VD33.13 ATX_VD33.15 BDB81.2 CB664.1
SC_ATX_VD33_LED: LDB19.1(A) RB601.2
SC_ATX_VD33_SW: CB658.2 LB1.1 RB598.1 UB70.3(SW)
SC_ATX_VD33_VOUT: BDB81.1 CB660.1 CB661.1 CB662.1 CB663.1 LB1.2 RB599.2 RB601.1
SC_BOOT_U70: RB597.1 UB70.1(BOOT)
SC_BOOT_U71: RB604.1 UB71.1(BOOT)
SC_BOOT_U73: RB618.1 UB73.1(BOOT)
SC_COMP_RC_U70: CB651.2 RB595.1
SC_COMP_RC_U71: CB666.2 RB623.1 RB624.1
SC_COMP_RC_U73: CB696.2 RB627.1 RB628.1
SC_COMP_U70: CB651.1 CB652.1 UB70.6(COMP)
SC_COMP_U71: CB666.1 CB667.1 UB71.6(COMP)
SC_COMP_U73: CB696.1 CB697.1 UB73.6(COMP)
SC_EN_U70: RB596.2 UB70.7(EN)
SC_EN_U71: RB603.2 UB71.7(EN)
SC_EN_U73: RB617.2 UB73.7(EN)
SC_FB_U70: CB660.2 RB599.1 RB600.1 UB70.5(FB)
SC_FB_U71: CB675.2 RB606.1 RB607.1 UB71.5(FB)
SC_FB_U73: CB705.2 RB620.1 RB621.1 UB73.5(FB)
SC_HOLD_UB1: RB205.2 UB5.3(~{WP}) UB5.7(~{HOLD})
SC_SS_U70: CB650.2 UB70.8(SS)
SC_SS_U71: CB665.2 UB71.8(SS)
SC_SS_U73: CB695.2 UB73.8(SS)
SC_SW_RC_U70: CB659.1 RB598.2
SC_SW_RC_U71: CB674.1 RB605.2
SC_SW_RC_U73: CB704.1 RB619.2
SC_VIN_U70: BDB80.2 CB653.2 CB654.1 CB655.1 RB596.1 UB70.2(VIN)
SC_VIN_U71: BDB82.2 CB668.2 CB669.1 CB670.1 RB603.1 UB71.2(VIN)
SC_VIN_U73: BDB86.2 CB698.2 CB699.1 CB700.1 RB617.1 UB73.2(VIN)
UR_0: U7.18(OUT1)
UR_1: U7.17(OUT2)
UR_2: U7.15(OUT3)
UR_3: U7.14(OUT4)
UR_4: U7.12(OUT5)
UR_5: U7.11(OUT6)
UR_6: U7.9(OUT7)
UR_7: U7.8(OUT8)
UR_8: U5.18(OUT1)
UR_9: U5.17(OUT2)
UR_10: U5.15(OUT3)
UR_11: U5.14(OUT4)
UR_12: U5.12(OUT5)
UR_13: U5.11(OUT6)
UR_14: U5.9(OUT7)
UR_15: U5.8(OUT8)
UR_16: U6.18(OUT1)
UR_17: U6.17(OUT2)
UR_18: U6.15(OUT3)
UR_19: U6.14(OUT4)
UR_20: U6.12(OUT5)
UR_21: U6.11(OUT6)
UR_22: U6.9(OUT7)
UR_23: U6.8(OUT8)
UR_24: U8.18(OUT1)
UR_25: U8.17(OUT2)
UR_26: U8.15(OUT3)
UR_27: U8.14(OUT4)
UR_28: U8.12(OUT5)
UR_29: U8.11(OUT6)
UR_30: U8.9(OUT7)
UR_31: U8.8(OUT8)
UR_32: U11.18(OUT1)
UR_33: U11.17(OUT2)
UR_34: U11.15(OUT3)
UR_35: U11.14(OUT4)
UR_36: U11.12(OUT5)
UR_37: U11.11(OUT6)
UR_38: U11.9(OUT7)
UR_39: U11.8(OUT8)
UR_40: U9.18(OUT1)
UR_41: U9.17(OUT2)
UR_42: U9.15(OUT3)
UR_43: U9.14(OUT4)
UR_44: U9.12(OUT5)
UR_45: U9.11(OUT6)
UR_46: U9.9(OUT7)
UR_47: U9.8(OUT8)
UR_48: U10.18(OUT1)
UR_49: U10.17(OUT2)
UR_50: U10.15(OUT3)
UR_51: U10.14(OUT4)
UR_52: U10.12(OUT5)
UR_53: U10.11(OUT6)
UR_54: U10.9(OUT7)
UR_55: U10.8(OUT8)
UR_56: U12.18(OUT1)
UR_57: U12.17(OUT2)
UR_58: U12.15(OUT3)
UR_59: U12.14(OUT4)
UR_60: U12.12(OUT5)
UR_61: U12.11(OUT6)
UR_62: U12.9(OUT7)
UR_63: U12.8(OUT8)
UR_64: U13.18(OUT1)
UR_65: U13.17(OUT2)
UR_66: U13.15(OUT3)
UR_67: U13.14(OUT4)
UR_68: U13.12(OUT5)
UR_69: U13.11(OUT6)
UR_70: U13.9(OUT7)
UR_71: U13.8(OUT8)
UR_72: U14.18(OUT1)
UR_73: U14.17(OUT2)
UR_74: U14.15(OUT3)
UR_75: U14.14(OUT4)
UR_76: U14.12(OUT5)
UR_77: U14.11(OUT6)
UR_78: U14.9(OUT7)
UR_79: U14.8(OUT8)
UR_80: U15.18(OUT1)
UR_81: U15.17(OUT2)
UR_82: U15.15(OUT3)
UR_83: U15.14(OUT4)
UR_84: U15.12(OUT5)
UR_85: U15.11(OUT6)
UR_86: U15.9(OUT7)
UR_87: U15.8(OUT8)
UR_88: U16.18(OUT1)
UR_89: U16.17(OUT2)
UR_90: U16.15(OUT3)
UR_91: U16.14(OUT4)
UR_92: U16.12(OUT5)
UR_93: U16.11(OUT6)
UR_94: U16.9(OUT7)
UR_95: U16.8(OUT8)
VN15: CT12.1 CT13.1 LDB6.2(B) TP_VN15.1(TP) ; also on sheet 38
VP5A: CT4.1 CT5.1 CT14.1 LRB2.1 RB205.1 TP_VP5A.1(TP) UB5.8(VCC) ; also on sheet 38
VP5B: C524.1 C525.1 C528.1 C539.1 C540.1 C541.1 C542.1 C543.1 C544.1 C545.1 C546.1 C547.1 C548.1 C549.1 C550.1 C551.1 C552.1 C553.1 C554.1 C555.1 CT2.1 CT3.1 LRB1.1 R327.2 R338.2 R342.2 R346.2 R347.2 R348.2 R349.2 R350.2 R351.2 R352.2 R353.2 R354.2 R355.2 R356.2 R357.2 R358.2 R359.2 R360.2 R361.2 R362.2 R363.2 R364.2 R365.2 R366.2 TP_VP5B.1(TP) U5.6(PDCD) U5.19(VS) U6.6(PDCD) U6.19(VS) U7.6(PDCD) U7.19(VS) U8.6(PDCD) U8.19(VS) U9.6(PDCD) U9.19(VS) U10.6(PDCD) U10.19(VS) U11.6(PDCD) U11.19(VS) U12.6(PDCD) U12.19(VS) U13.6(PDCD) U13.19(VS) U14.6(PDCD) U14.19(VS) U15.6(PDCD) U15.19(VS) U16.6(PDCD) U16.19(VS) ; also on sheet 38
VP12: CT6.1 CT7.1 LRB3.2 TP_VP12.1(TP) VDD12_ATX.2 VDD12_ATX.4 ; also on sheet 2 3 4 5 6 7 8 9 10 11 12 13 14 15 16 17 18 19 20 21 22 23 24 25 26 38
VP15: CT10.1 CT11.1 LRB5.2 TP_VP15.1(TP) ; also on sheet 38
VP24: CT8.1 CT9.1 LRB4.2 TP_VP24.1(TP) ; also on sheet 38
N7344580: CB658.1 RB597.2
N7347819: CB673.1 RB604.2
N7350256: CB703.1 RB618.2
N16079151: LDB1.1(A) LRB1.2
N16079317: LDB2.1(A) LRB2.2
N16079993: LDB3.1(A) LRB3.1
N16083795: LDB4.1(A) LRB4.1
N16083921: LDB5.1(A) LRB5.1
N16084055: LDB6.1(A) LRB6.1
N19745084: U8.5(DOUT) U11.3(DIN)
N20743418: U5.5(DOUT) U6.3(DIN)
N20743561: R327.1 U7.1(~{RESET})
N20743722: R346.1 U5.1(~{RESET})
N20743738: R338.1 U5.20(~{FLAG})
N20743807: R342.1 U7.20(~{FLAG})
N20754919: U6.5(DOUT) U8.3(DIN)
N20754925: R347.1 U6.1(~{RESET})
N20754928: R365.1 U6.20(~{FLAG})
N20754936: U5.3(DIN) U7.5(DOUT)
N20754977: R348.1 U8.1(~{RESET})
N20754980: R366.1 U8.20(~{FLAG})
N25278384: U12.5(DOUT) U13.3(DIN)
N25278501: U10.5(DOUT) U12.3(DIN)
N25278513: R355.1 U10.1(~{RESET})
N25278527: R350.1 U10.20(~{FLAG})
N25278533: U9.5(DOUT) U10.3(DIN)
N25278541: U9.3(DIN) U11.5(DOUT)
N25278621: R356.1 U12.1(~{RESET})
N25278627: R349.1 U12.20(~{FLAG})
N25278841: R354.1 U11.1(~{RESET})
N25278855: R352.1 U9.1(~{RESET})
N25278861: R353.1 U9.20(~{FLAG})
N25278867: R351.1 U11.20(~{FLAG})
N25280768: U15.5(DOUT) U16.3(DIN)
N25280780: R363.1 U15.1(~{RESET})
N25280794: R358.1 U15.20(~{FLAG})
N25280800: U14.5(DOUT) U15.3(DIN)
N25280808: U13.5(DOUT) U14.3(DIN)
N25280888: R364.1 U16.1(~{RESET})
N25280894: R357.1 U16.20(~{FLAG})
N25281108: R362.1 U13.1(~{RESET})
N25281122: R360.1 U14.1(~{RESET})
N25281128: R361.1 U14.20(~{FLAG})
N25281134: R359.1 U13.20(~{FLAG})

Not connected (* = marked no-connect by the designer): HOLE_CABLE3 1(NP1)*; HOLE_CABLE4 1(NP1)*; JB1 8(Power_good)* 9(+5V_standby)* 12(-12V)* 18(-5V)*; P1 K10(10)* K12(12)* L1(1)* L3(3)* M2(2)* M4(4)* M12(12)* N6(6)* N12(12)* O1(1)* O7(7)* Q1(1)* Q7(7)* R10(10)* R12(12)* S9(9)* S11(11)* T10(10)* T12(12)* U9(9)* U11(11)* V6(6)* V12(12)* W1(1)* W7(7)* X6(6)* X12(12)* Y1(1)* Y7(7)* Z2(2)* Z4(4)* Z6(6)* Z8(8)* Z10(10)* Z12(12)*; P2 K10(10)* M4(4)* M12(12)* X10(10)* Z4(4)* Z12(12)*; P4 K10(10)* K12(12)* L1(1)* L3(3)* L5(5)* L7(7)* L9(9)* L11(11)* M2(2)* M4(4)* M6(6)* M8(8)* M10(10)* M12(12)* N2(2)* N4(4)* N6(6)* N8(8)* N10(10)* N12(12)* O1(1)* O3(3)* O5(5)* O7(7)* O9(9)* O11(11)* P2(2)* P4(4)* P6(6)* P8(8)* P10(10)* P12(12)* Q1(1)* Q3(3)* Q5(5)* Q7(7)* Q9(9)* Q11(11)* R2(2)* R4(4)* R6(6)* R8(8)* R10(10)* R12(12)* S1(1)* S3(3)* S5(5)* S7(7)* S9(9)* S11(11)* T2(2)* T4(4)* T6(6)* T8(8)* T10(10)* T12(12)* U1(1)* U3(3)* U5(5)* U7(7)* U9(9)* U11(11)* V2(2)* V4(4)* V6(6)* V8(8)* V10(10)* V12(12)* W1(1)* W3(3)* W5(5)* W7(7)* W9(9)* W11(11)* X2(2)* X4(4)* X6(6)* X8(8)* X10(10)* X12(12)* Y1(1)* Y3(3)* Y5(5)* Y7(7)* Y9(9)* Y11(11)* Z2(2)* Z4(4)* Z6(6)* Z8(8)* Z10(10)* Z12(12)*; P5 K10(10)* M4(4)* M12(12)* X10(10)* Z4(4)* Z12(12)*; SCREW3 NGH1* NGH2* NGH3* NGH4* NGH5* NGH6* SC1* SC2* SC3* SC4* SC5* SC6* SC7* SC8* SC9* SC10* SC11* SC12* SC13* SC14* SC15* SC16* SC17* SC18* SC19* SC20* SC21* SC22* SC23* SC24* SC25* SC26* SC27* SC28* SC29* SC30* SC31* SC32* SC33* SC34* SC35* SC36* SC37* SC38* SC39* SC40* SC41* SC42* SC43* SC44* SC45* SC46*; SWB1 1* 4* 5*

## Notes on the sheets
sheet 27
- Board Power Source: ATX Power
- Mark on Board
  ============
  VDD12_ATX
- Top
- ATX_VD33
- Mark on Board
  ============
  ATX_VD33
- ATX_VD1V8
- Mark on Board
  ============
  ATX_VD1V8
- ATX_VD0V9
- Mark on Board
  ============
  ATX_VD0V9
sheet 28
- VP5B¹q¬y¸û¤j(7.5A)¡A¦]¦¹Àu¥ý³s±µVP5B
- CAL_SPI_SL0
- CAL_SPI_DIN0
- CAL_SPI_CK0
- CAL_SPI_DO0
sheet 29
- LB Power
sheet 31
- P1_DPS64_10_H
- P1_HDAVO8_H
sheet 32
- P2_LPC2_H
- P2_LPC0_H
sheet 33
- P4_DPS32_23_H
- P4_DPS32_24_H
sheet 34
- P5_LPC1_H
- P5_LPC3_H
